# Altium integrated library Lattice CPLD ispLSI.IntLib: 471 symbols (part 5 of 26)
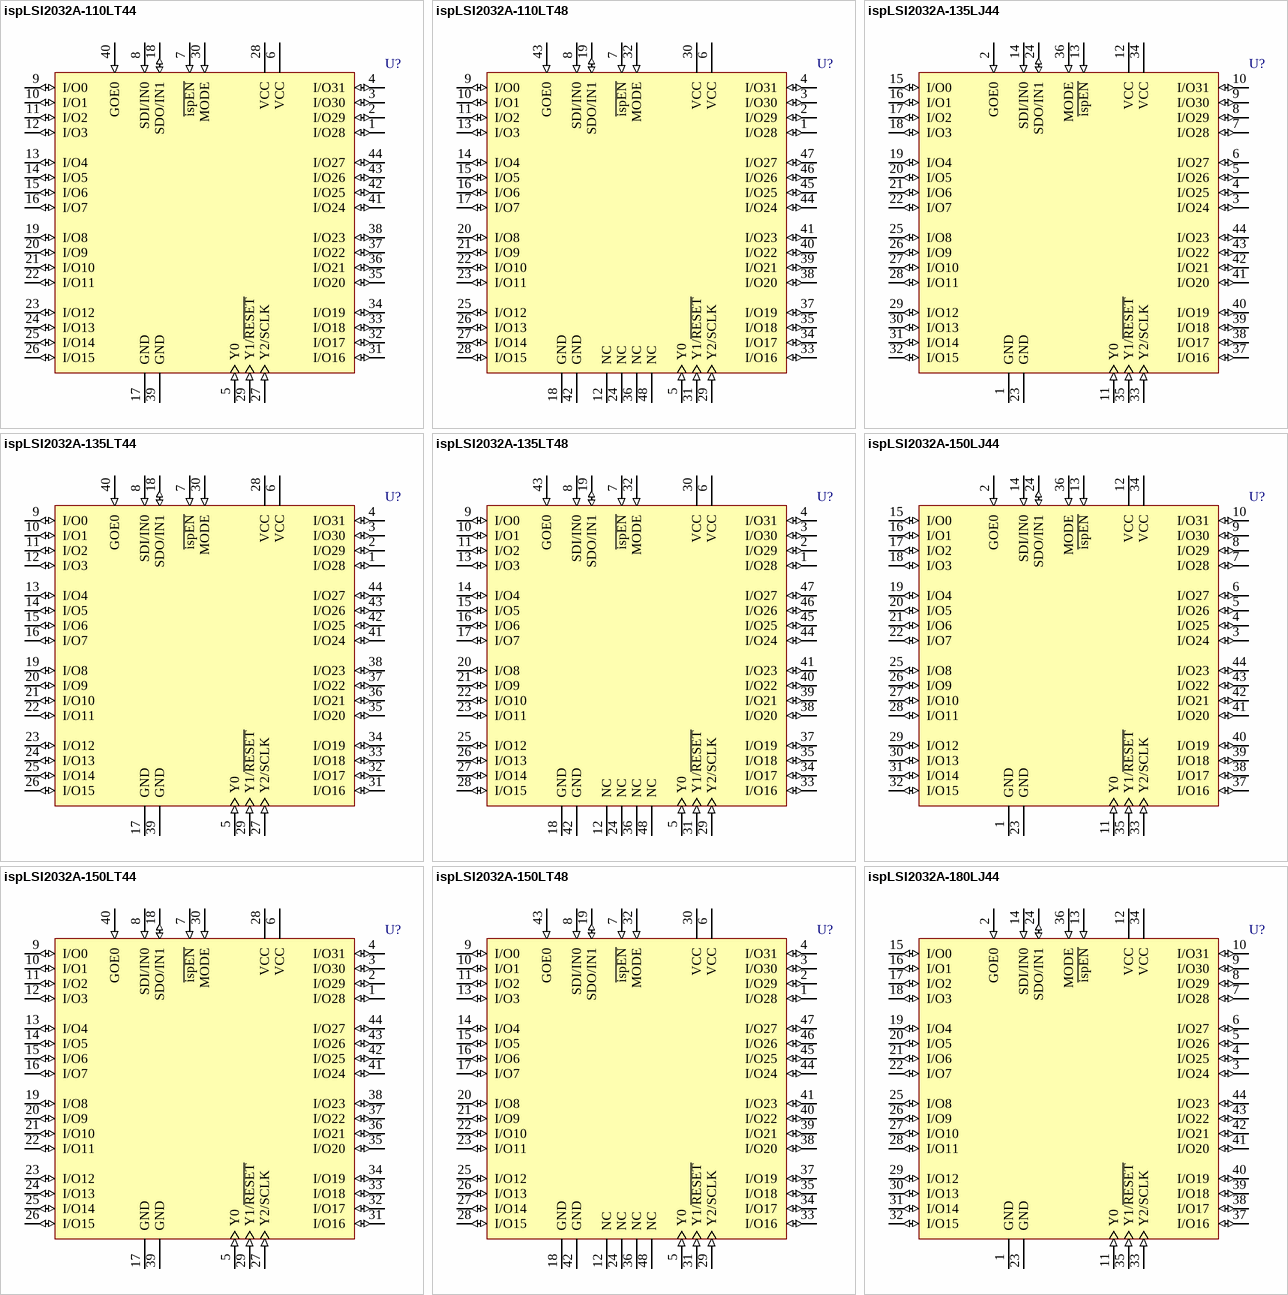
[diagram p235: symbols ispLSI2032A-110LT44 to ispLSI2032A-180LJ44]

## ispLSI2032A-150LT44
designator U?
In-System Programmable High-Density PLD; Note: Pins 8, 18 and 27 have dual function capability.
footprint TQFP44_N (Thin QFP, 44-Leads, Body 10x10mm, Pitch 0.8mm, IPC Medium Density)
footprint TQFP44_L (Thin QFP, 44-Leads, Body 10x10mm, Pitch 0.8mm, IPC High Density)
footprint TQFP44_M (Thin QFP, 44-Leads, Body 10x10mm, Pitch 0.8mm, IPC Low Density)
3D model 2032A-TQFP44 (44-Pin Thin Quad Flat Pack 0.8 mm Pitch)
pins: 1 I/O28 (io), 2 I/O29 (io), 3 I/O30 (io), 4 I/O31 (io), 5 Y0 (in), 6 VCC (power), 7 ~{ispEN} (in), 8 SDI/IN0 (in), 9 I/O0 (io), 10 I/O1 (io), 11 I/O2 (io), 12 I/O3 (io), 13 I/O4 (io), 14 I/O5 (io), 15 I/O6 (io), 16 I/O7 (io), 17 GND (power), 18 SDO/IN1 (io), 19 I/O8 (io), 20 I/O9 (io), 21 I/O10 (io), 22 I/O11 (io), 23 I/O12 (io), 24 I/O13 (io), 25 I/O14 (io), 26 I/O15 (io), 27 Y2/SCLK (in), 28 VCC (power), 29 Y1/~{RESET} (in), 30 MODE (in), 31 I/O16 (io), 32 I/O17 (io), 33 I/O18 (io), 34 I/O19 (io), 35 I/O20 (io), 36 I/O21 (io), 37 I/O22 (io), 38 I/O23 (io), 39 GND (power), 40 GOE0 (in), 41 I/O24 (io), 42 I/O25 (io), 43 I/O26 (io), 44 I/O27 (io)

## ispLSI2032A-150LT48
designator U?
In-System Programmable High-Density PLD; Note: Pins 8, 19 and 29 have dual function capability.
footprint TQFP48_N (Thin QFP, 48-Leads, Body 7x7mm, Pitch 0.5mm, IPC Medium Density)
footprint TQFP48_L (Thin QFP, 48-Leads, Body 7x7mm, Pitch 0.5mm, IPC High Density)
footprint TQFP48_M (Thin QFP, 48-Leads, Body 7x7mm, Pitch 0.5mm, IPC Low Density)
3D model 2032A-TQFP48 (48-Pin Thin Quad Flat Pack 0.5 mm Pitch)
pins: 1 I/O28 (io), 2 I/O29 (io), 3 I/O30 (io), 4 I/O31 (io), 5 Y0 (in), 6 VCC (power), 7 ~{ispEN} (in), 8 SDI/IN0 (in), 9 I/O0 (io), 10 I/O1 (io), 11 I/O2 (io), 12 NC, 13 I/O3 (io), 14 I/O4 (io), 15 I/O5 (io), 16 I/O6 (io), 17 I/O7 (io), 18 GND (power), 19 SDO/IN1 (io), 20 I/O8 (io), 21 I/O9 (io), 22 I/O10 (io), 23 I/O11 (io), 24 NC, 25 I/O12 (io), 26 I/O13 (io), 27 I/O14 (io), 28 I/O15 (io), 29 Y2/SCLK (in), 30 VCC (power), 31 Y1/~{RESET} (in), 32 MODE (in), 33 I/O16 (io), 34 I/O17 (io), 35 I/O18 (io), 36 NC, 37 I/O19 (io), 38 I/O20 (io), 39 I/O21 (io), 40 I/O22 (io), 41 I/O23 (io), 42 GND (power), 43 GOE0 (in), 44 I/O24 (io), 45 I/O25 (io), 46 I/O26 (io), 47 I/O27 (io), 48 NC

## ispLSI2032A-180LJ44
designator U?
In-System Programmable High-Density PLD; Note: Pins 14, 24 and 33 have dual function capability.
footprint PLCC44_N (Leaded Chip Carrier, 44-Leads, Body 16.6x16.6mm, Pitch 1.27mm, IPC Medium Density)
footprint PLCC44_L (Leaded Chip Carrier, 44-Leads, Body 16.6x16.6mm, Pitch 1.27mm, IPC High Density)
footprint PLCC44_M (Leaded Chip Carrier, 44-Leads, Body 16.6x16.6mm, Pitch 1.27mm, IPC Low Density)
3D model 2032A-PLCC44 (44-Pin Leaded Chip Carrier 1.27 mm Pitch)
pins: 1 GND (power), 2 GOE0 (in), 3 I/O24 (io), 4 I/O25 (io), 5 I/O26 (io), 6 I/O27 (io), 7 I/O28 (io), 8 I/O29 (io), 9 I/O30 (io), 10 I/O31 (io), 11 Y0 (in), 12 VCC (power), 13 ~{ispEN} (in), 14 SDI/IN0 (in), 15 I/O0 (io), 16 I/O1 (io), 17 I/O2 (io), 18 I/O3 (io), 19 I/O4 (io), 20 I/O5 (io), 21 I/O6 (io), 22 I/O7 (io), 23 GND (power), 24 SDO/IN1 (io), 25 I/O8 (io), 26 I/O9 (io), 27 I/O10 (io), 28 I/O11 (io), 29 I/O12 (io), 30 I/O13 (io), 31 I/O14 (io), 32 I/O15 (io), 33 Y2/SCLK (in), 34 VCC (power), 35 Y1/~{RESET} (in), 36 MODE (in), 37 I/O16 (io), 38 I/O17 (io), 39 I/O18 (io), 40 I/O19 (io), 41 I/O20 (io), 42 I/O21 (io), 43 I/O22 (io), 44 I/O23 (io)

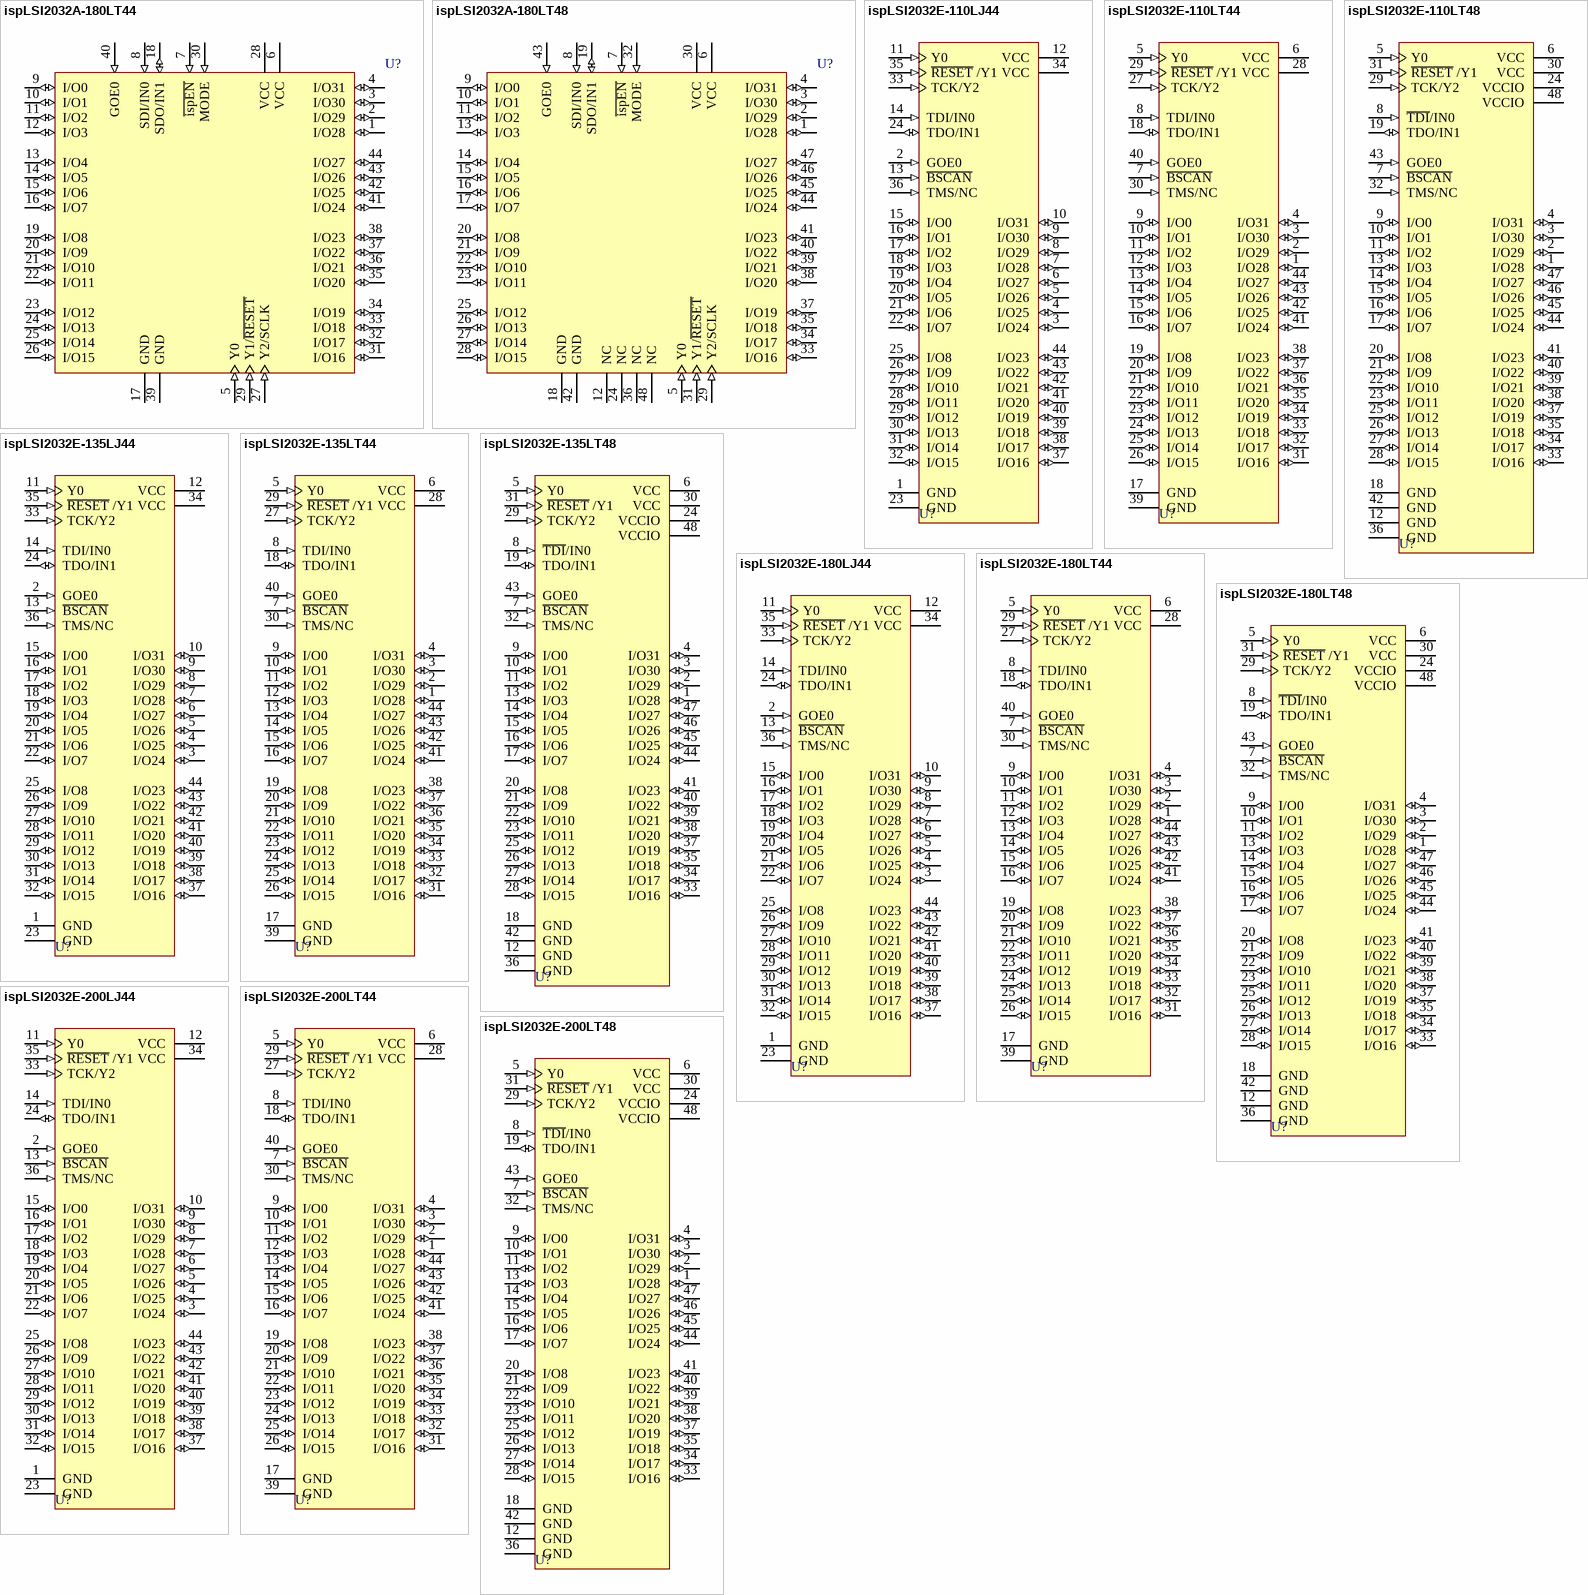
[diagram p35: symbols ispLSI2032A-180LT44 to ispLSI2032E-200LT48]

## ispLSI2032A-180LT44
designator U?
In-System Programmable High-Density PLD; Note: Pins 8, 18 and 27 have dual function capability.
footprint TQFP44_N (Thin QFP, 44-Leads, Body 10x10mm, Pitch 0.8mm, IPC Medium Density)
footprint TQFP44_L (Thin QFP, 44-Leads, Body 10x10mm, Pitch 0.8mm, IPC High Density)
footprint TQFP44_M (Thin QFP, 44-Leads, Body 10x10mm, Pitch 0.8mm, IPC Low Density)
3D model 2032A-TQFP44 (44-Pin Thin Quad Flat Pack 0.8 mm Pitch)
pins: 1 I/O28 (io), 2 I/O29 (io), 3 I/O30 (io), 4 I/O31 (io), 5 Y0 (in), 6 VCC (power), 7 ~{ispEN} (in), 8 SDI/IN0 (in), 9 I/O0 (io), 10 I/O1 (io), 11 I/O2 (io), 12 I/O3 (io), 13 I/O4 (io), 14 I/O5 (io), 15 I/O6 (io), 16 I/O7 (io), 17 GND (power), 18 SDO/IN1 (io), 19 I/O8 (io), 20 I/O9 (io), 21 I/O10 (io), 22 I/O11 (io), 23 I/O12 (io), 24 I/O13 (io), 25 I/O14 (io), 26 I/O15 (io), 27 Y2/SCLK (in), 28 VCC (power), 29 Y1/~{RESET} (in), 30 MODE (in), 31 I/O16 (io), 32 I/O17 (io), 33 I/O18 (io), 34 I/O19 (io), 35 I/O20 (io), 36 I/O21 (io), 37 I/O22 (io), 38 I/O23 (io), 39 GND (power), 40 GOE0 (in), 41 I/O24 (io), 42 I/O25 (io), 43 I/O26 (io), 44 I/O27 (io)

## ispLSI2032A-180LT48
designator U?
In-System Programmable High-Density PLD; Note: Pins 8, 19 and 29 have dual function capability.
footprint TQFP48_N (Thin QFP, 48-Leads, Body 7x7mm, Pitch 0.5mm, IPC Medium Density)
footprint TQFP48_L (Thin QFP, 48-Leads, Body 7x7mm, Pitch 0.5mm, IPC High Density)
footprint TQFP48_M (Thin QFP, 48-Leads, Body 7x7mm, Pitch 0.5mm, IPC Low Density)
3D model 2032A-TQFP48 (48-Pin Thin Quad Flat Pack 0.5 mm Pitch)
pins: 1 I/O28 (io), 2 I/O29 (io), 3 I/O30 (io), 4 I/O31 (io), 5 Y0 (in), 6 VCC (power), 7 ~{ispEN} (in), 8 SDI/IN0 (in), 9 I/O0 (io), 10 I/O1 (io), 11 I/O2 (io), 12 NC, 13 I/O3 (io), 14 I/O4 (io), 15 I/O5 (io), 16 I/O6 (io), 17 I/O7 (io), 18 GND (power), 19 SDO/IN1 (io), 20 I/O8 (io), 21 I/O9 (io), 22 I/O10 (io), 23 I/O11 (io), 24 NC, 25 I/O12 (io), 26 I/O13 (io), 27 I/O14 (io), 28 I/O15 (io), 29 Y2/SCLK (in), 30 VCC (power), 31 Y1/~{RESET} (in), 32 MODE (in), 33 I/O16 (io), 34 I/O17 (io), 35 I/O18 (io), 36 NC, 37 I/O19 (io), 38 I/O20 (io), 39 I/O21 (io), 40 I/O22 (io), 41 I/O23 (io), 42 GND (power), 43 GOE0 (in), 44 I/O24 (io), 45 I/O25 (io), 46 I/O26 (io), 47 I/O27 (io), 48 NC

## ispLSI2032E-110LJ44
designator U?
In-System Programmable SuperFAST High Density PLD
footprint PLCC44_N (Leaded Chip Carrier, 44-Leads, Body 16.6x16.6mm, Pitch 1.27mm, IPC Medium Density)
footprint PLCC44_L (Leaded Chip Carrier, 44-Leads, Body 16.6x16.6mm, Pitch 1.27mm, IPC High Density)
footprint PLCC44_M (Leaded Chip Carrier, 44-Leads, Body 16.6x16.6mm, Pitch 1.27mm, IPC Low Density)
3D model 2032E-PLCC44 (44-Pin Leaded Chip Carrier 1.27 mm Pitch)
pins: 1 GND (power), 2 GOE0 (in), 3 I/O24 (io), 4 I/O25 (io), 5 I/O26 (io), 6 I/O27 (io), 7 I/O28 (io), 8 I/O29 (io), 9 I/O30 (io), 10 I/O31 (io), 11 Y0 (in), 12 VCC (power), 13 ~{BSCAN} (in), 14 TDI/IN0 (in), 15 I/O0 (io), 16 I/O1 (io), 17 I/O2 (io), 18 I/O3 (io), 19 I/O4 (io), 20 I/O5 (io), 21 I/O6 (io), 22 I/O7 (io), 23 GND (power), 24 TDO/IN1 (io), 25 I/O8 (io), 26 I/O9 (io), 27 I/O10 (io), 28 I/O11 (io), 29 I/O12 (io), 30 I/O13 (io), 31 I/O14 (io), 32 I/O15 (io), 33 TCK/Y2 (in), 34 VCC (power), 35 ~{RESET} /Y1 (in), 36 TMS/NC (in), 37 I/O16 (io), 38 I/O17 (io), 39 I/O18 (io), 40 I/O19 (io), 41 I/O20 (io), 42 I/O21 (io), 43 I/O22 (io), 44 I/O23 (io)

## ispLSI2032E-110LT44
designator U?
In-System Programmable SuperFAST High Density PLD
footprint TQFP44_N (Thin QFP, 44-Leads, Body 10x10mm, Pitch 0.8mm, IPC Medium Density)
footprint TQFP44_L (Thin QFP, 44-Leads, Body 10x10mm, Pitch 0.8mm, IPC High Density)
footprint TQFP44_M (Thin QFP, 44-Leads, Body 10x10mm, Pitch 0.8mm, IPC Low Density)
3D model 2032E-TQFP44 (44-Pin Thin Quad Flat Pack 0.8 mm Pitch)
pins: 1 I/O28 (io), 2 I/O29 (io), 3 I/O30 (io), 4 I/O31 (io), 5 Y0 (in), 6 VCC (power), 7 ~{BSCAN} (in), 8 TDI/IN0 (in), 9 I/O0 (io), 10 I/O1 (io), 11 I/O2 (io), 12 I/O3 (io), 13 I/O4 (io), 14 I/O5 (io), 15 I/O6 (io), 16 I/O7 (io), 17 GND (power), 18 TDO/IN1 (io), 19 I/O8 (io), 20 I/O9 (io), 21 I/O10 (io), 22 I/O11 (io), 23 I/O12 (io), 24 I/O13 (io), 25 I/O14 (io), 26 I/O15 (io), 27 TCK/Y2 (in), 28 VCC (power), 29 ~{RESET} /Y1 (in), 30 TMS/NC (in), 31 I/O16 (io), 32 I/O17 (io), 33 I/O18 (io), 34 I/O19 (io), 35 I/O20 (io), 36 I/O21 (io), 37 I/O22 (io), 38 I/O23 (io), 39 GND (power), 40 GOE0 (in), 41 I/O24 (io), 42 I/O25 (io), 43 I/O26 (io), 44 I/O27 (io)

## ispLSI2032E-110LT48
designator U?
In-System Programmable SuperFAST High Density PLD
footprint TQFP48_N (Thin QFP, 48-Leads, Body 7x7mm, Pitch 0.5mm, IPC Medium Density)
footprint TQFP48_L (Thin QFP, 48-Leads, Body 7x7mm, Pitch 0.5mm, IPC High Density)
footprint TQFP48_M (Thin QFP, 48-Leads, Body 7x7mm, Pitch 0.5mm, IPC Low Density)
3D model 2032E-TQFP48 (48-Pin Thin Quad Flat Pack 0.5 mm Pitch)
pins: 1 I/O28 (io), 2 I/O29 (io), 3 I/O30 (io), 4 I/O31 (io), 5 Y0 (in), 6 VCC (power), 7 ~{BSCAN} (in), 8 ~{TDI}/IN0 (in), 9 I/O0 (io), 10 I/O1 (io), 11 I/O2 (io), 12 GND (power), 13 I/O3 (io), 14 I/O4 (io), 15 I/O5 (io), 16 I/O6 (io), 17 I/O7 (io), 18 GND (power), 19 TDO/IN1 (io), 20 I/O8 (io), 21 I/O9 (io), 22 I/O10 (io), 23 I/O11 (io), 24 VCCIO (power), 25 I/O12 (io), 26 I/O13 (io), 27 I/O14 (io), 28 I/O15 (io), 29 TCK/Y2 (in), 30 VCC (power), 31 ~{RESET} /Y1 (in), 32 TMS/NC (in), 33 I/O16 (io), 34 I/O17 (io), 35 I/O18 (io), 36 GND (power), 37 I/O19 (io), 38 I/O20 (io), 39 I/O21 (io), 40 I/O22 (io), 41 I/O23 (io), 42 GND (power), 43 GOE0 (in), 44 I/O24 (io), 45 I/O25 (io), 46 I/O26 (io), 47 I/O27 (io), 48 VCCIO (power)

## ispLSI2032E-135LJ44
designator U?
In-System Programmable SuperFAST High Density PLD
footprint PLCC44_N (Leaded Chip Carrier, 44-Leads, Body 16.6x16.6mm, Pitch 1.27mm, IPC Medium Density)
footprint PLCC44_L (Leaded Chip Carrier, 44-Leads, Body 16.6x16.6mm, Pitch 1.27mm, IPC High Density)
footprint PLCC44_M (Leaded Chip Carrier, 44-Leads, Body 16.6x16.6mm, Pitch 1.27mm, IPC Low Density)
3D model 2032E-PLCC44 (44-Pin Leaded Chip Carrier 1.27 mm Pitch)
pins: 1 GND (power), 2 GOE0 (in), 3 I/O24 (io), 4 I/O25 (io), 5 I/O26 (io), 6 I/O27 (io), 7 I/O28 (io), 8 I/O29 (io), 9 I/O30 (io), 10 I/O31 (io), 11 Y0 (in), 12 VCC (power), 13 ~{BSCAN} (in), 14 TDI/IN0 (in), 15 I/O0 (io), 16 I/O1 (io), 17 I/O2 (io), 18 I/O3 (io), 19 I/O4 (io), 20 I/O5 (io), 21 I/O6 (io), 22 I/O7 (io), 23 GND (power), 24 TDO/IN1 (io), 25 I/O8 (io), 26 I/O9 (io), 27 I/O10 (io), 28 I/O11 (io), 29 I/O12 (io), 30 I/O13 (io), 31 I/O14 (io), 32 I/O15 (io), 33 TCK/Y2 (in), 34 VCC (power), 35 ~{RESET} /Y1 (in), 36 TMS/NC (in), 37 I/O16 (io), 38 I/O17 (io), 39 I/O18 (io), 40 I/O19 (io), 41 I/O20 (io), 42 I/O21 (io), 43 I/O22 (io), 44 I/O23 (io)

## ispLSI2032E-135LT44
designator U?
In-System Programmable SuperFAST High Density PLD
footprint TQFP44_N (Thin QFP, 44-Leads, Body 10x10mm, Pitch 0.8mm, IPC Medium Density)
footprint TQFP44_L (Thin QFP, 44-Leads, Body 10x10mm, Pitch 0.8mm, IPC High Density)
footprint TQFP44_M (Thin QFP, 44-Leads, Body 10x10mm, Pitch 0.8mm, IPC Low Density)
3D model 2032E-TQFP44 (44-Pin Thin Quad Flat Pack 0.8 mm Pitch)
pins: 1 I/O28 (io), 2 I/O29 (io), 3 I/O30 (io), 4 I/O31 (io), 5 Y0 (in), 6 VCC (power), 7 ~{BSCAN} (in), 8 TDI/IN0 (in), 9 I/O0 (io), 10 I/O1 (io), 11 I/O2 (io), 12 I/O3 (io), 13 I/O4 (io), 14 I/O5 (io), 15 I/O6 (io), 16 I/O7 (io), 17 GND (power), 18 TDO/IN1 (io), 19 I/O8 (io), 20 I/O9 (io), 21 I/O10 (io), 22 I/O11 (io), 23 I/O12 (io), 24 I/O13 (io), 25 I/O14 (io), 26 I/O15 (io), 27 TCK/Y2 (in), 28 VCC (power), 29 ~{RESET} /Y1 (in), 30 TMS/NC (in), 31 I/O16 (io), 32 I/O17 (io), 33 I/O18 (io), 34 I/O19 (io), 35 I/O20 (io), 36 I/O21 (io), 37 I/O22 (io), 38 I/O23 (io), 39 GND (power), 40 GOE0 (in), 41 I/O24 (io), 42 I/O25 (io), 43 I/O26 (io), 44 I/O27 (io)

## ispLSI2032E-135LT48
designator U?
In-System Programmable SuperFAST High Density PLD
footprint TQFP48_N (Thin QFP, 48-Leads, Body 7x7mm, Pitch 0.5mm, IPC Medium Density)
footprint TQFP48_L (Thin QFP, 48-Leads, Body 7x7mm, Pitch 0.5mm, IPC High Density)
footprint TQFP48_M (Thin QFP, 48-Leads, Body 7x7mm, Pitch 0.5mm, IPC Low Density)
3D model 2032E-TQFP48 (48-Pin Thin Quad Flat Pack 0.5 mm Pitch)
pins: 1 I/O28 (io), 2 I/O29 (io), 3 I/O30 (io), 4 I/O31 (io), 5 Y0 (in), 6 VCC (power), 7 ~{BSCAN} (in), 8 ~{TDI}/IN0 (in), 9 I/O0 (io), 10 I/O1 (io), 11 I/O2 (io), 12 GND (power), 13 I/O3 (io), 14 I/O4 (io), 15 I/O5 (io), 16 I/O6 (io), 17 I/O7 (io), 18 GND (power), 19 TDO/IN1 (io), 20 I/O8 (io), 21 I/O9 (io), 22 I/O10 (io), 23 I/O11 (io), 24 VCCIO (power), 25 I/O12 (io), 26 I/O13 (io), 27 I/O14 (io), 28 I/O15 (io), 29 TCK/Y2 (in), 30 VCC (power), 31 ~{RESET} /Y1 (in), 32 TMS/NC (in), 33 I/O16 (io), 34 I/O17 (io), 35 I/O18 (io), 36 GND (power), 37 I/O19 (io), 38 I/O20 (io), 39 I/O21 (io), 40 I/O22 (io), 41 I/O23 (io), 42 GND (power), 43 GOE0 (in), 44 I/O24 (io), 45 I/O25 (io), 46 I/O26 (io), 47 I/O27 (io), 48 VCCIO (power)

## ispLSI2032E-180LJ44
designator U?
In-System Programmable SuperFAST High Density PLD
footprint PLCC44_N (Leaded Chip Carrier, 44-Leads, Body 16.6x16.6mm, Pitch 1.27mm, IPC Medium Density)
footprint PLCC44_L (Leaded Chip Carrier, 44-Leads, Body 16.6x16.6mm, Pitch 1.27mm, IPC High Density)
footprint PLCC44_M (Leaded Chip Carrier, 44-Leads, Body 16.6x16.6mm, Pitch 1.27mm, IPC Low Density)
3D model 2032E-PLCC44 (44-Pin Leaded Chip Carrier 1.27 mm Pitch)
pins: 1 GND (power), 2 GOE0 (in), 3 I/O24 (io), 4 I/O25 (io), 5 I/O26 (io), 6 I/O27 (io), 7 I/O28 (io), 8 I/O29 (io), 9 I/O30 (io), 10 I/O31 (io), 11 Y0 (in), 12 VCC (power), 13 ~{BSCAN} (in), 14 TDI/IN0 (in), 15 I/O0 (io), 16 I/O1 (io), 17 I/O2 (io), 18 I/O3 (io), 19 I/O4 (io), 20 I/O5 (io), 21 I/O6 (io), 22 I/O7 (io), 23 GND (power), 24 TDO/IN1 (io), 25 I/O8 (io), 26 I/O9 (io), 27 I/O10 (io), 28 I/O11 (io), 29 I/O12 (io), 30 I/O13 (io), 31 I/O14 (io), 32 I/O15 (io), 33 TCK/Y2 (in), 34 VCC (power), 35 ~{RESET} /Y1 (in), 36 TMS/NC (in), 37 I/O16 (io), 38 I/O17 (io), 39 I/O18 (io), 40 I/O19 (io), 41 I/O20 (io), 42 I/O21 (io), 43 I/O22 (io), 44 I/O23 (io)

## ispLSI2032E-180LT44
designator U?
In-System Programmable SuperFAST High Density PLD
footprint TQFP44_N (Thin QFP, 44-Leads, Body 10x10mm, Pitch 0.8mm, IPC Medium Density)
footprint TQFP44_L (Thin QFP, 44-Leads, Body 10x10mm, Pitch 0.8mm, IPC High Density)
footprint TQFP44_M (Thin QFP, 44-Leads, Body 10x10mm, Pitch 0.8mm, IPC Low Density)
3D model 2032E-TQFP44 (44-Pin Thin Quad Flat Pack 0.8 mm Pitch)
pins: 1 I/O28 (io), 2 I/O29 (io), 3 I/O30 (io), 4 I/O31 (io), 5 Y0 (in), 6 VCC (power), 7 ~{BSCAN} (in), 8 TDI/IN0 (in), 9 I/O0 (io), 10 I/O1 (io), 11 I/O2 (io), 12 I/O3 (io), 13 I/O4 (io), 14 I/O5 (io), 15 I/O6 (io), 16 I/O7 (io), 17 GND (power), 18 TDO/IN1 (io), 19 I/O8 (io), 20 I/O9 (io), 21 I/O10 (io), 22 I/O11 (io), 23 I/O12 (io), 24 I/O13 (io), 25 I/O14 (io), 26 I/O15 (io), 27 TCK/Y2 (in), 28 VCC (power), 29 ~{RESET} /Y1 (in), 30 TMS/NC (in), 31 I/O16 (io), 32 I/O17 (io), 33 I/O18 (io), 34 I/O19 (io), 35 I/O20 (io), 36 I/O21 (io), 37 I/O22 (io), 38 I/O23 (io), 39 GND (power), 40 GOE0 (in), 41 I/O24 (io), 42 I/O25 (io), 43 I/O26 (io), 44 I/O27 (io)

## ispLSI2032E-180LT48
designator U?
In-System Programmable SuperFAST High Density PLD
footprint TQFP48_N (Thin QFP, 48-Leads, Body 7x7mm, Pitch 0.5mm, IPC Medium Density)
footprint TQFP48_L (Thin QFP, 48-Leads, Body 7x7mm, Pitch 0.5mm, IPC High Density)
footprint TQFP48_M (Thin QFP, 48-Leads, Body 7x7mm, Pitch 0.5mm, IPC Low Density)
3D model 2032E-TQFP48 (48-Pin Thin Quad Flat Pack 0.5 mm Pitch)
pins: 1 I/O28 (io), 2 I/O29 (io), 3 I/O30 (io), 4 I/O31 (io), 5 Y0 (in), 6 VCC (power), 7 ~{BSCAN} (in), 8 ~{TDI}/IN0 (in), 9 I/O0 (io), 10 I/O1 (io), 11 I/O2 (io), 12 GND (power), 13 I/O3 (io), 14 I/O4 (io), 15 I/O5 (io), 16 I/O6 (io), 17 I/O7 (io), 18 GND (power), 19 TDO/IN1 (io), 20 I/O8 (io), 21 I/O9 (io), 22 I/O10 (io), 23 I/O11 (io), 24 VCCIO (power), 25 I/O12 (io), 26 I/O13 (io), 27 I/O14 (io), 28 I/O15 (io), 29 TCK/Y2 (in), 30 VCC (power), 31 ~{RESET} /Y1 (in), 32 TMS/NC (in), 33 I/O16 (io), 34 I/O17 (io), 35 I/O18 (io), 36 GND (power), 37 I/O19 (io), 38 I/O20 (io), 39 I/O21 (io), 40 I/O22 (io), 41 I/O23 (io), 42 GND (power), 43 GOE0 (in), 44 I/O24 (io), 45 I/O25 (io), 46 I/O26 (io), 47 I/O27 (io), 48 VCCIO (power)

## ispLSI2032E-200LJ44
designator U?
In-System Programmable SuperFAST High Density PLD
footprint PLCC44_N (Leaded Chip Carrier, 44-Leads, Body 16.6x16.6mm, Pitch 1.27mm, IPC Medium Density)
footprint PLCC44_L (Leaded Chip Carrier, 44-Leads, Body 16.6x16.6mm, Pitch 1.27mm, IPC High Density)
footprint PLCC44_M (Leaded Chip Carrier, 44-Leads, Body 16.6x16.6mm, Pitch 1.27mm, IPC Low Density)
3D model 2032E-PLCC44 (44-Pin Leaded Chip Carrier 1.27 mm Pitch)
pins: 1 GND (power), 2 GOE0 (in), 3 I/O24 (io), 4 I/O25 (io), 5 I/O26 (io), 6 I/O27 (io), 7 I/O28 (io), 8 I/O29 (io), 9 I/O30 (io), 10 I/O31 (io), 11 Y0 (in), 12 VCC (power), 13 ~{BSCAN} (in), 14 TDI/IN0 (in), 15 I/O0 (io), 16 I/O1 (io), 17 I/O2 (io), 18 I/O3 (io), 19 I/O4 (io), 20 I/O5 (io), 21 I/O6 (io), 22 I/O7 (io), 23 GND (power), 24 TDO/IN1 (io), 25 I/O8 (io), 26 I/O9 (io), 27 I/O10 (io), 28 I/O11 (io), 29 I/O12 (io), 30 I/O13 (io), 31 I/O14 (io), 32 I/O15 (io), 33 TCK/Y2 (in), 34 VCC (power), 35 ~{RESET} /Y1 (in), 36 TMS/NC (in), 37 I/O16 (io), 38 I/O17 (io), 39 I/O18 (io), 40 I/O19 (io), 41 I/O20 (io), 42 I/O21 (io), 43 I/O22 (io), 44 I/O23 (io)

## ispLSI2032E-200LT44
designator U?
In-System Programmable SuperFAST High Density PLD
footprint TQFP44_N (Thin QFP, 44-Leads, Body 10x10mm, Pitch 0.8mm, IPC Medium Density)
footprint TQFP44_L (Thin QFP, 44-Leads, Body 10x10mm, Pitch 0.8mm, IPC High Density)
footprint TQFP44_M (Thin QFP, 44-Leads, Body 10x10mm, Pitch 0.8mm, IPC Low Density)
3D model 2032E-TQFP44 (44-Pin Thin Quad Flat Pack 0.8 mm Pitch)
pins: 1 I/O28 (io), 2 I/O29 (io), 3 I/O30 (io), 4 I/O31 (io), 5 Y0 (in), 6 VCC (power), 7 ~{BSCAN} (in), 8 TDI/IN0 (in), 9 I/O0 (io), 10 I/O1 (io), 11 I/O2 (io), 12 I/O3 (io), 13 I/O4 (io), 14 I/O5 (io), 15 I/O6 (io), 16 I/O7 (io), 17 GND (power), 18 TDO/IN1 (io), 19 I/O8 (io), 20 I/O9 (io), 21 I/O10 (io), 22 I/O11 (io), 23 I/O12 (io), 24 I/O13 (io), 25 I/O14 (io), 26 I/O15 (io), 27 TCK/Y2 (in), 28 VCC (power), 29 ~{RESET} /Y1 (in), 30 TMS/NC (in), 31 I/O16 (io), 32 I/O17 (io), 33 I/O18 (io), 34 I/O19 (io), 35 I/O20 (io), 36 I/O21 (io), 37 I/O22 (io), 38 I/O23 (io), 39 GND (power), 40 GOE0 (in), 41 I/O24 (io), 42 I/O25 (io), 43 I/O26 (io), 44 I/O27 (io)

## ispLSI2032E-200LT48
designator U?
In-System Programmable SuperFAST High Density PLD
footprint TQFP48_N (Thin QFP, 48-Leads, Body 7x7mm, Pitch 0.5mm, IPC Medium Density)
footprint TQFP48_L (Thin QFP, 48-Leads, Body 7x7mm, Pitch 0.5mm, IPC High Density)
footprint TQFP48_M (Thin QFP, 48-Leads, Body 7x7mm, Pitch 0.5mm, IPC Low Density)
3D model 2032E-TQFP48 (48-Pin Thin Quad Flat Pack 0.5 mm Pitch)
pins: 1 I/O28 (io), 2 I/O29 (io), 3 I/O30 (io), 4 I/O31 (io), 5 Y0 (in), 6 VCC (power), 7 ~{BSCAN} (in), 8 ~{TDI}/IN0 (in), 9 I/O0 (io), 10 I/O1 (io), 11 I/O2 (io), 12 GND (power), 13 I/O3 (io), 14 I/O4 (io), 15 I/O5 (io), 16 I/O6 (io), 17 I/O7 (io), 18 GND (power), 19 TDO/IN1 (io), 20 I/O8 (io), 21 I/O9 (io), 22 I/O10 (io), 23 I/O11 (io), 24 VCCIO (power), 25 I/O12 (io), 26 I/O13 (io), 27 I/O14 (io), 28 I/O15 (io), 29 TCK/Y2 (in), 30 VCC (power), 31 ~{RESET} /Y1 (in), 32 TMS/NC (in), 33 I/O16 (io), 34 I/O17 (io), 35 I/O18 (io), 36 GND (power), 37 I/O19 (io), 38 I/O20 (io), 39 I/O21 (io), 40 I/O22 (io), 41 I/O23 (io), 42 GND (power), 43 GOE0 (in), 44 I/O24 (io), 45 I/O25 (io), 46 I/O26 (io), 47 I/O27 (io), 48 VCCIO (power)

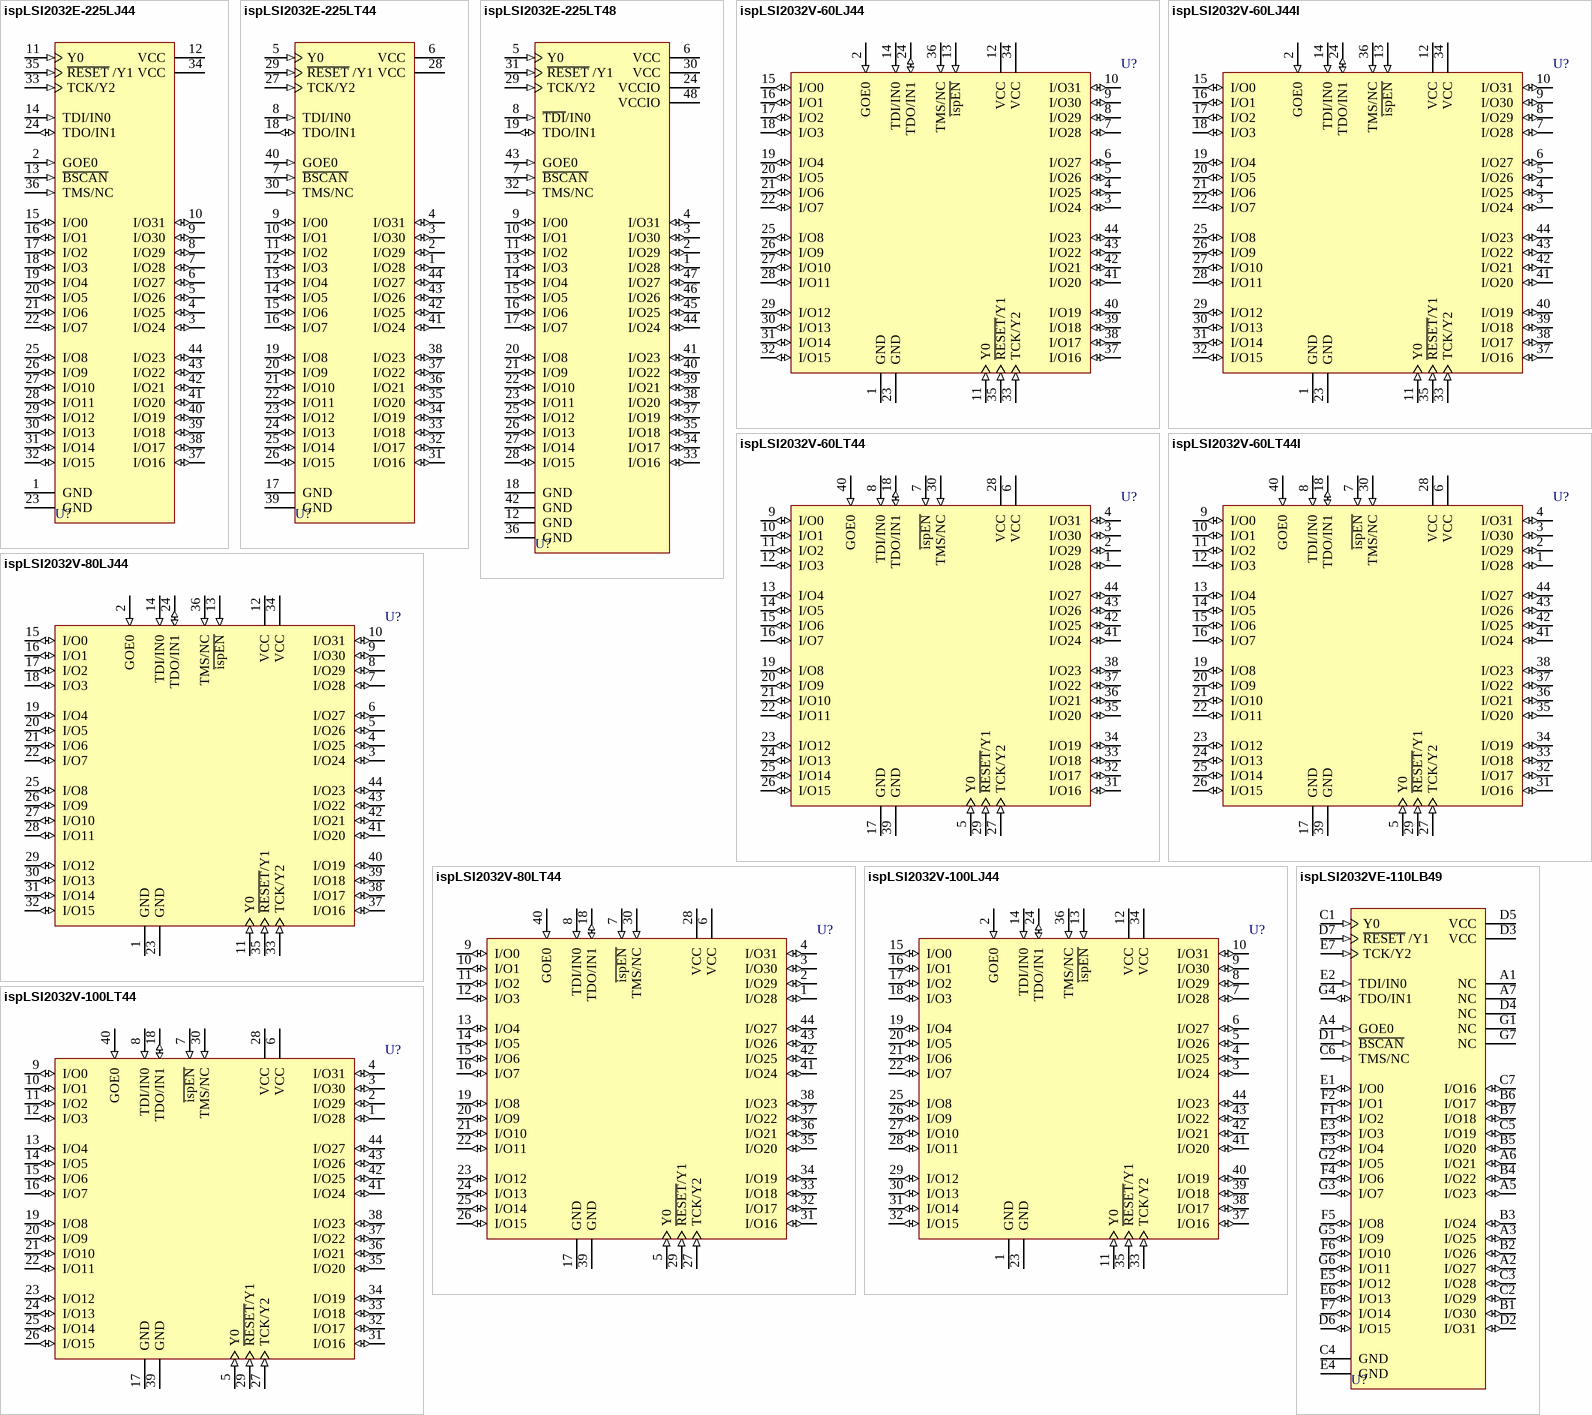
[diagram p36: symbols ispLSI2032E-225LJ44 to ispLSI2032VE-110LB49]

## ispLSI2032E-225LJ44
designator U?
In-System Programmable SuperFAST High Density PLD
footprint PLCC44_N (Leaded Chip Carrier, 44-Leads, Body 16.6x16.6mm, Pitch 1.27mm, IPC Medium Density)
footprint PLCC44_L (Leaded Chip Carrier, 44-Leads, Body 16.6x16.6mm, Pitch 1.27mm, IPC High Density)
footprint PLCC44_M (Leaded Chip Carrier, 44-Leads, Body 16.6x16.6mm, Pitch 1.27mm, IPC Low Density)
3D model 2032E-PLCC44 (44-Pin Leaded Chip Carrier 1.27 mm Pitch)
pins: 1 GND (power), 2 GOE0 (in), 3 I/O24 (io), 4 I/O25 (io), 5 I/O26 (io), 6 I/O27 (io), 7 I/O28 (io), 8 I/O29 (io), 9 I/O30 (io), 10 I/O31 (io), 11 Y0 (in), 12 VCC (power), 13 ~{BSCAN} (in), 14 TDI/IN0 (in), 15 I/O0 (io), 16 I/O1 (io), 17 I/O2 (io), 18 I/O3 (io), 19 I/O4 (io), 20 I/O5 (io), 21 I/O6 (io), 22 I/O7 (io), 23 GND (power), 24 TDO/IN1 (io), 25 I/O8 (io), 26 I/O9 (io), 27 I/O10 (io), 28 I/O11 (io), 29 I/O12 (io), 30 I/O13 (io), 31 I/O14 (io), 32 I/O15 (io), 33 TCK/Y2 (in), 34 VCC (power), 35 ~{RESET} /Y1 (in), 36 TMS/NC (in), 37 I/O16 (io), 38 I/O17 (io), 39 I/O18 (io), 40 I/O19 (io), 41 I/O20 (io), 42 I/O21 (io), 43 I/O22 (io), 44 I/O23 (io)

## ispLSI2032E-225LT44
designator U?
In-System Programmable SuperFAST High Density PLD
footprint TQFP44_N (Thin QFP, 44-Leads, Body 10x10mm, Pitch 0.8mm, IPC Medium Density)
footprint TQFP44_L (Thin QFP, 44-Leads, Body 10x10mm, Pitch 0.8mm, IPC High Density)
footprint TQFP44_M (Thin QFP, 44-Leads, Body 10x10mm, Pitch 0.8mm, IPC Low Density)
3D model 2032E-TQFP44 (44-Pin Thin Quad Flat Pack 0.8 mm Pitch)
pins: 1 I/O28 (io), 2 I/O29 (io), 3 I/O30 (io), 4 I/O31 (io), 5 Y0 (in), 6 VCC (power), 7 ~{BSCAN} (in), 8 TDI/IN0 (in), 9 I/O0 (io), 10 I/O1 (io), 11 I/O2 (io), 12 I/O3 (io), 13 I/O4 (io), 14 I/O5 (io), 15 I/O6 (io), 16 I/O7 (io), 17 GND (power), 18 TDO/IN1 (io), 19 I/O8 (io), 20 I/O9 (io), 21 I/O10 (io), 22 I/O11 (io), 23 I/O12 (io), 24 I/O13 (io), 25 I/O14 (io), 26 I/O15 (io), 27 TCK/Y2 (in), 28 VCC (power), 29 ~{RESET} /Y1 (in), 30 TMS/NC (in), 31 I/O16 (io), 32 I/O17 (io), 33 I/O18 (io), 34 I/O19 (io), 35 I/O20 (io), 36 I/O21 (io), 37 I/O22 (io), 38 I/O23 (io), 39 GND (power), 40 GOE0 (in), 41 I/O24 (io), 42 I/O25 (io), 43 I/O26 (io), 44 I/O27 (io)

## ispLSI2032E-225LT48
designator U?
In-System Programmable SuperFAST High Density PLD
footprint TQFP48_N (Thin QFP, 48-Leads, Body 7x7mm, Pitch 0.5mm, IPC Medium Density)
footprint TQFP48_L (Thin QFP, 48-Leads, Body 7x7mm, Pitch 0.5mm, IPC High Density)
footprint TQFP48_M (Thin QFP, 48-Leads, Body 7x7mm, Pitch 0.5mm, IPC Low Density)
3D model 2032E-TQFP48 (48-Pin Thin Quad Flat Pack 0.5 mm Pitch)
pins: 1 I/O28 (io), 2 I/O29 (io), 3 I/O30 (io), 4 I/O31 (io), 5 Y0 (in), 6 VCC (power), 7 ~{BSCAN} (in), 8 ~{TDI}/IN0 (in), 9 I/O0 (io), 10 I/O1 (io), 11 I/O2 (io), 12 GND (power), 13 I/O3 (io), 14 I/O4 (io), 15 I/O5 (io), 16 I/O6 (io), 17 I/O7 (io), 18 GND (power), 19 TDO/IN1 (io), 20 I/O8 (io), 21 I/O9 (io), 22 I/O10 (io), 23 I/O11 (io), 24 VCCIO (power), 25 I/O12 (io), 26 I/O13 (io), 27 I/O14 (io), 28 I/O15 (io), 29 TCK/Y2 (in), 30 VCC (power), 31 ~{RESET} /Y1 (in), 32 TMS/NC (in), 33 I/O16 (io), 34 I/O17 (io), 35 I/O18 (io), 36 GND (power), 37 I/O19 (io), 38 I/O20 (io), 39 I/O21 (io), 40 I/O22 (io), 41 I/O23 (io), 42 GND (power), 43 GOE0 (in), 44 I/O24 (io), 45 I/O25 (io), 46 I/O26 (io), 47 I/O27 (io), 48 VCCIO (power)

## ispLSI2032V-60LJ44
designator U?
3.3V High-Density Programmable Logic
footprint PLCC44_N (Leaded Chip Carrier, 44-Leads, Body 16.6x16.6mm, Pitch 1.27mm, IPC Medium Density)
footprint PLCC44_L (Leaded Chip Carrier, 44-Leads, Body 16.6x16.6mm, Pitch 1.27mm, IPC High Density)
footprint PLCC44_M (Leaded Chip Carrier, 44-Leads, Body 16.6x16.6mm, Pitch 1.27mm, IPC Low Density)
3D model 2032V-PLCC44 (44-Pin Leaded Chip Carrier 1.27 mm Pitch)
pins: 1 GND (power), 2 GOE0 (in), 3 I/O24 (io), 4 I/O25 (io), 5 I/O26 (io), 6 I/O27 (io), 7 I/O28 (io), 8 I/O29 (io), 9 I/O30 (io), 10 I/O31 (io), 11 Y0 (in), 12 VCC (power), 13 ~{ispEN} (in), 14 TDI/IN0 (in), 15 I/O0 (io), 16 I/O1 (io), 17 I/O2 (io), 18 I/O3 (io), 19 I/O4 (io), 20 I/O5 (io), 21 I/O6 (io), 22 I/O7 (io), 23 GND (power), 24 TDO/IN1 (io), 25 I/O8 (io), 26 I/O9 (io), 27 I/O10 (io), 28 I/O11 (io), 29 I/O12 (io), 30 I/O13 (io), 31 I/O14 (io), 32 I/O15 (io), 33 TCK/Y2 (in), 34 VCC (power), 35 ~{RESET}/Y1 (in), 36 TMS/NC (in), 37 I/O16 (io), 38 I/O17 (io), 39 I/O18 (io), 40 I/O19 (io), 41 I/O20 (io), 42 I/O21 (io), 43 I/O22 (io), 44 I/O23 (io)

## ispLSI2032V-60LJ44I
designator U?
3.3V High-Density Programmable Logic
footprint PLCC44_N (Leaded Chip Carrier, 44-Leads, Body 16.6x16.6mm, Pitch 1.27mm, IPC Medium Density)
footprint PLCC44_L (Leaded Chip Carrier, 44-Leads, Body 16.6x16.6mm, Pitch 1.27mm, IPC High Density)
footprint PLCC44_M (Leaded Chip Carrier, 44-Leads, Body 16.6x16.6mm, Pitch 1.27mm, IPC Low Density)
3D model 2032V-PLCC44 (44-Pin Leaded Chip Carrier 1.27 mm Pitch)
pins: 1 GND (power), 2 GOE0 (in), 3 I/O24 (io), 4 I/O25 (io), 5 I/O26 (io), 6 I/O27 (io), 7 I/O28 (io), 8 I/O29 (io), 9 I/O30 (io), 10 I/O31 (io), 11 Y0 (in), 12 VCC (power), 13 ~{ispEN} (in), 14 TDI/IN0 (in), 15 I/O0 (io), 16 I/O1 (io), 17 I/O2 (io), 18 I/O3 (io), 19 I/O4 (io), 20 I/O5 (io), 21 I/O6 (io), 22 I/O7 (io), 23 GND (power), 24 TDO/IN1 (io), 25 I/O8 (io), 26 I/O9 (io), 27 I/O10 (io), 28 I/O11 (io), 29 I/O12 (io), 30 I/O13 (io), 31 I/O14 (io), 32 I/O15 (io), 33 TCK/Y2 (in), 34 VCC (power), 35 ~{RESET}/Y1 (in), 36 TMS/NC (in), 37 I/O16 (io), 38 I/O17 (io), 39 I/O18 (io), 40 I/O19 (io), 41 I/O20 (io), 42 I/O21 (io), 43 I/O22 (io), 44 I/O23 (io)

## ispLSI2032V-60LT44
designator U?
3.3V High-Density Programmable Logic
footprint TQFP44_N (Thin QFP, 44-Leads, Body 10x10mm, Pitch 0.8mm, IPC Medium Density)
footprint TQFP44_L (Thin QFP, 44-Leads, Body 10x10mm, Pitch 0.8mm, IPC High Density)
footprint TQFP44_M (Thin QFP, 44-Leads, Body 10x10mm, Pitch 0.8mm, IPC Low Density)
3D model 2032V-TQFP44 (44-Pin Thin Quad Flat Pack 0.8 mm Pitch)
pins: 1 I/O28 (io), 2 I/O29 (io), 3 I/O30 (io), 4 I/O31 (io), 5 Y0 (in), 6 VCC (power), 7 ~{ispEN} (in), 8 TDI/IN0 (in), 9 I/O0 (io), 10 I/O1 (io), 11 I/O2 (io), 12 I/O3 (io), 13 I/O4 (io), 14 I/O5 (io), 15 I/O6 (io), 16 I/O7 (io), 17 GND (power), 18 TDO/IN1 (io), 19 I/O8 (io), 20 I/O9 (io), 21 I/O10 (io), 22 I/O11 (io), 23 I/O12 (io), 24 I/O13 (io), 25 I/O14 (io), 26 I/O15 (io), 27 TCK/Y2 (in), 28 VCC (power), 29 ~{RESET}/Y1 (in), 30 TMS/NC (in), 31 I/O16 (io), 32 I/O17 (io), 33 I/O18 (io), 34 I/O19 (io), 35 I/O20 (io), 36 I/O21 (io), 37 I/O22 (io), 38 I/O23 (io), 39 GND (power), 40 GOE0 (in), 41 I/O24 (io), 42 I/O25 (io), 43 I/O26 (io), 44 I/O27 (io)

## ispLSI2032V-60LT44I
designator U?
3.3V High-Density Programmable Logic
footprint TQFP44_N (Thin QFP, 44-Leads, Body 10x10mm, Pitch 0.8mm, IPC Medium Density)
footprint TQFP44_L (Thin QFP, 44-Leads, Body 10x10mm, Pitch 0.8mm, IPC High Density)
footprint TQFP44_M (Thin QFP, 44-Leads, Body 10x10mm, Pitch 0.8mm, IPC Low Density)
3D model 2032V-TQFP44 (44-Pin Thin Quad Flat Pack 0.8 mm Pitch)
pins: 1 I/O28 (io), 2 I/O29 (io), 3 I/O30 (io), 4 I/O31 (io), 5 Y0 (in), 6 VCC (power), 7 ~{ispEN} (in), 8 TDI/IN0 (in), 9 I/O0 (io), 10 I/O1 (io), 11 I/O2 (io), 12 I/O3 (io), 13 I/O4 (io), 14 I/O5 (io), 15 I/O6 (io), 16 I/O7 (io), 17 GND (power), 18 TDO/IN1 (io), 19 I/O8 (io), 20 I/O9 (io), 21 I/O10 (io), 22 I/O11 (io), 23 I/O12 (io), 24 I/O13 (io), 25 I/O14 (io), 26 I/O15 (io), 27 TCK/Y2 (in), 28 VCC (power), 29 ~{RESET}/Y1 (in), 30 TMS/NC (in), 31 I/O16 (io), 32 I/O17 (io), 33 I/O18 (io), 34 I/O19 (io), 35 I/O20 (io), 36 I/O21 (io), 37 I/O22 (io), 38 I/O23 (io), 39 GND (power), 40 GOE0 (in), 41 I/O24 (io), 42 I/O25 (io), 43 I/O26 (io), 44 I/O27 (io)

## ispLSI2032V-80LJ44
designator U?
3.3V High-Density Programmable Logic
footprint PLCC44_N (Leaded Chip Carrier, 44-Leads, Body 16.6x16.6mm, Pitch 1.27mm, IPC Medium Density)
footprint PLCC44_L (Leaded Chip Carrier, 44-Leads, Body 16.6x16.6mm, Pitch 1.27mm, IPC High Density)
footprint PLCC44_M (Leaded Chip Carrier, 44-Leads, Body 16.6x16.6mm, Pitch 1.27mm, IPC Low Density)
3D model 2032V-PLCC44 (44-Pin Leaded Chip Carrier 1.27 mm Pitch)
pins: 1 GND (power), 2 GOE0 (in), 3 I/O24 (io), 4 I/O25 (io), 5 I/O26 (io), 6 I/O27 (io), 7 I/O28 (io), 8 I/O29 (io), 9 I/O30 (io), 10 I/O31 (io), 11 Y0 (in), 12 VCC (power), 13 ~{ispEN} (in), 14 TDI/IN0 (in), 15 I/O0 (io), 16 I/O1 (io), 17 I/O2 (io), 18 I/O3 (io), 19 I/O4 (io), 20 I/O5 (io), 21 I/O6 (io), 22 I/O7 (io), 23 GND (power), 24 TDO/IN1 (io), 25 I/O8 (io), 26 I/O9 (io), 27 I/O10 (io), 28 I/O11 (io), 29 I/O12 (io), 30 I/O13 (io), 31 I/O14 (io), 32 I/O15 (io), 33 TCK/Y2 (in), 34 VCC (power), 35 ~{RESET}/Y1 (in), 36 TMS/NC (in), 37 I/O16 (io), 38 I/O17 (io), 39 I/O18 (io), 40 I/O19 (io), 41 I/O20 (io), 42 I/O21 (io), 43 I/O22 (io), 44 I/O23 (io)

## ispLSI2032V-80LT44
designator U?
3.3V High-Density Programmable Logic
footprint TQFP44_N (Thin QFP, 44-Leads, Body 10x10mm, Pitch 0.8mm, IPC Medium Density)
footprint TQFP44_L (Thin QFP, 44-Leads, Body 10x10mm, Pitch 0.8mm, IPC High Density)
footprint TQFP44_M (Thin QFP, 44-Leads, Body 10x10mm, Pitch 0.8mm, IPC Low Density)
3D model 2032V-TQFP44 (44-Pin Thin Quad Flat Pack 0.8 mm Pitch)
pins: 1 I/O28 (io), 2 I/O29 (io), 3 I/O30 (io), 4 I/O31 (io), 5 Y0 (in), 6 VCC (power), 7 ~{ispEN} (in), 8 TDI/IN0 (in), 9 I/O0 (io), 10 I/O1 (io), 11 I/O2 (io), 12 I/O3 (io), 13 I/O4 (io), 14 I/O5 (io), 15 I/O6 (io), 16 I/O7 (io), 17 GND (power), 18 TDO/IN1 (io), 19 I/O8 (io), 20 I/O9 (io), 21 I/O10 (io), 22 I/O11 (io), 23 I/O12 (io), 24 I/O13 (io), 25 I/O14 (io), 26 I/O15 (io), 27 TCK/Y2 (in), 28 VCC (power), 29 ~{RESET}/Y1 (in), 30 TMS/NC (in), 31 I/O16 (io), 32 I/O17 (io), 33 I/O18 (io), 34 I/O19 (io), 35 I/O20 (io), 36 I/O21 (io), 37 I/O22 (io), 38 I/O23 (io), 39 GND (power), 40 GOE0 (in), 41 I/O24 (io), 42 I/O25 (io), 43 I/O26 (io), 44 I/O27 (io)

## ispLSI2032V-100LJ44
designator U?
3.3V High-Density Programmable Logic
footprint PLCC44_N (Leaded Chip Carrier, 44-Leads, Body 16.6x16.6mm, Pitch 1.27mm, IPC Medium Density)
footprint PLCC44_L (Leaded Chip Carrier, 44-Leads, Body 16.6x16.6mm, Pitch 1.27mm, IPC High Density)
footprint PLCC44_M (Leaded Chip Carrier, 44-Leads, Body 16.6x16.6mm, Pitch 1.27mm, IPC Low Density)
3D model 2032V-PLCC44 (44-Pin Leaded Chip Carrier 1.27 mm Pitch)
pins: 1 GND (power), 2 GOE0 (in), 3 I/O24 (io), 4 I/O25 (io), 5 I/O26 (io), 6 I/O27 (io), 7 I/O28 (io), 8 I/O29 (io), 9 I/O30 (io), 10 I/O31 (io), 11 Y0 (in), 12 VCC (power), 13 ~{ispEN} (in), 14 TDI/IN0 (in), 15 I/O0 (io), 16 I/O1 (io), 17 I/O2 (io), 18 I/O3 (io), 19 I/O4 (io), 20 I/O5 (io), 21 I/O6 (io), 22 I/O7 (io), 23 GND (power), 24 TDO/IN1 (io), 25 I/O8 (io), 26 I/O9 (io), 27 I/O10 (io), 28 I/O11 (io), 29 I/O12 (io), 30 I/O13 (io), 31 I/O14 (io), 32 I/O15 (io), 33 TCK/Y2 (in), 34 VCC (power), 35 ~{RESET}/Y1 (in), 36 TMS/NC (in), 37 I/O16 (io), 38 I/O17 (io), 39 I/O18 (io), 40 I/O19 (io), 41 I/O20 (io), 42 I/O21 (io), 43 I/O22 (io), 44 I/O23 (io)

## ispLSI2032V-100LT44
designator U?
3.3V High-Density Programmable Logic
footprint TQFP44_N (Thin QFP, 44-Leads, Body 10x10mm, Pitch 0.8mm, IPC Medium Density)
footprint TQFP44_L (Thin QFP, 44-Leads, Body 10x10mm, Pitch 0.8mm, IPC High Density)
footprint TQFP44_M (Thin QFP, 44-Leads, Body 10x10mm, Pitch 0.8mm, IPC Low Density)
3D model 2032V-TQFP44 (44-Pin Thin Quad Flat Pack 0.8 mm Pitch)
pins: 1 I/O28 (io), 2 I/O29 (io), 3 I/O30 (io), 4 I/O31 (io), 5 Y0 (in), 6 VCC (power), 7 ~{ispEN} (in), 8 TDI/IN0 (in), 9 I/O0 (io), 10 I/O1 (io), 11 I/O2 (io), 12 I/O3 (io), 13 I/O4 (io), 14 I/O5 (io), 15 I/O6 (io), 16 I/O7 (io), 17 GND (power), 18 TDO/IN1 (io), 19 I/O8 (io), 20 I/O9 (io), 21 I/O10 (io), 22 I/O11 (io), 23 I/O12 (io), 24 I/O13 (io), 25 I/O14 (io), 26 I/O15 (io), 27 TCK/Y2 (in), 28 VCC (power), 29 ~{RESET}/Y1 (in), 30 TMS/NC (in), 31 I/O16 (io), 32 I/O17 (io), 33 I/O18 (io), 34 I/O19 (io), 35 I/O20 (io), 36 I/O21 (io), 37 I/O22 (io), 38 I/O23 (io), 39 GND (power), 40 GOE0 (in), 41 I/O24 (io), 42 I/O25 (io), 43 I/O26 (io), 44 I/O27 (io)

## ispLSI2032VE-110LB49
designator U?
3.3V In-System Programmable High Density SuperFAST PLD
footprint caBGA49 (BGA, 49-Leads, Body 7x7mm, Pitch 0.8mm)
3D model 2032VE-caBGA49 (49-Ball Chip Array Ball Grid Array (caBGA49))
pins: A1 NC, A2 I/O27 (io), A3 I/O25 (io), A4 GOE0 (in), A5 I/O23 (io), A6 I/O21 (io), A7 NC, B1 I/O30 (io), B2 I/O26 (io), B3 I/O24 (io), B4 I/O22 (io), B5 I/O20 (io), B6 I/O17 (io), B7 I/O18 (io), C1 Y0 (in), C2 I/O29 (io), C3 I/O28 (io), C4 GND (power), C5 I/O19 (io), C6 TMS/NC (in), C7 I/O16 (io), D1 ~{BSCAN} (in), D2 I/O31 (io), D3 VCC (power), D4 NC, D5 VCC (power), D6 I/O15 (io), D7 ~{RESET} /Y1 (in), E1 I/O0 (io), E2 TDI/IN0 (in), E3 I/O3 (io), E4 GND (power), E5 I/O12 (io), E6 I/O13 (io), E7 TCK/Y2 (in), F1 I/O2 (io), F2 I/O1 (io), F3 I/O4 (io), F4 I/O6 (io), F5 I/O8 (io), F6 I/O10 (io), F7 I/O14 (io), G1 NC, G2 I/O5 (io), G3 I/O7 (io), G4 TDO/IN1 (io), G5 I/O9 (io), G6 I/O11 (io), G7 NC

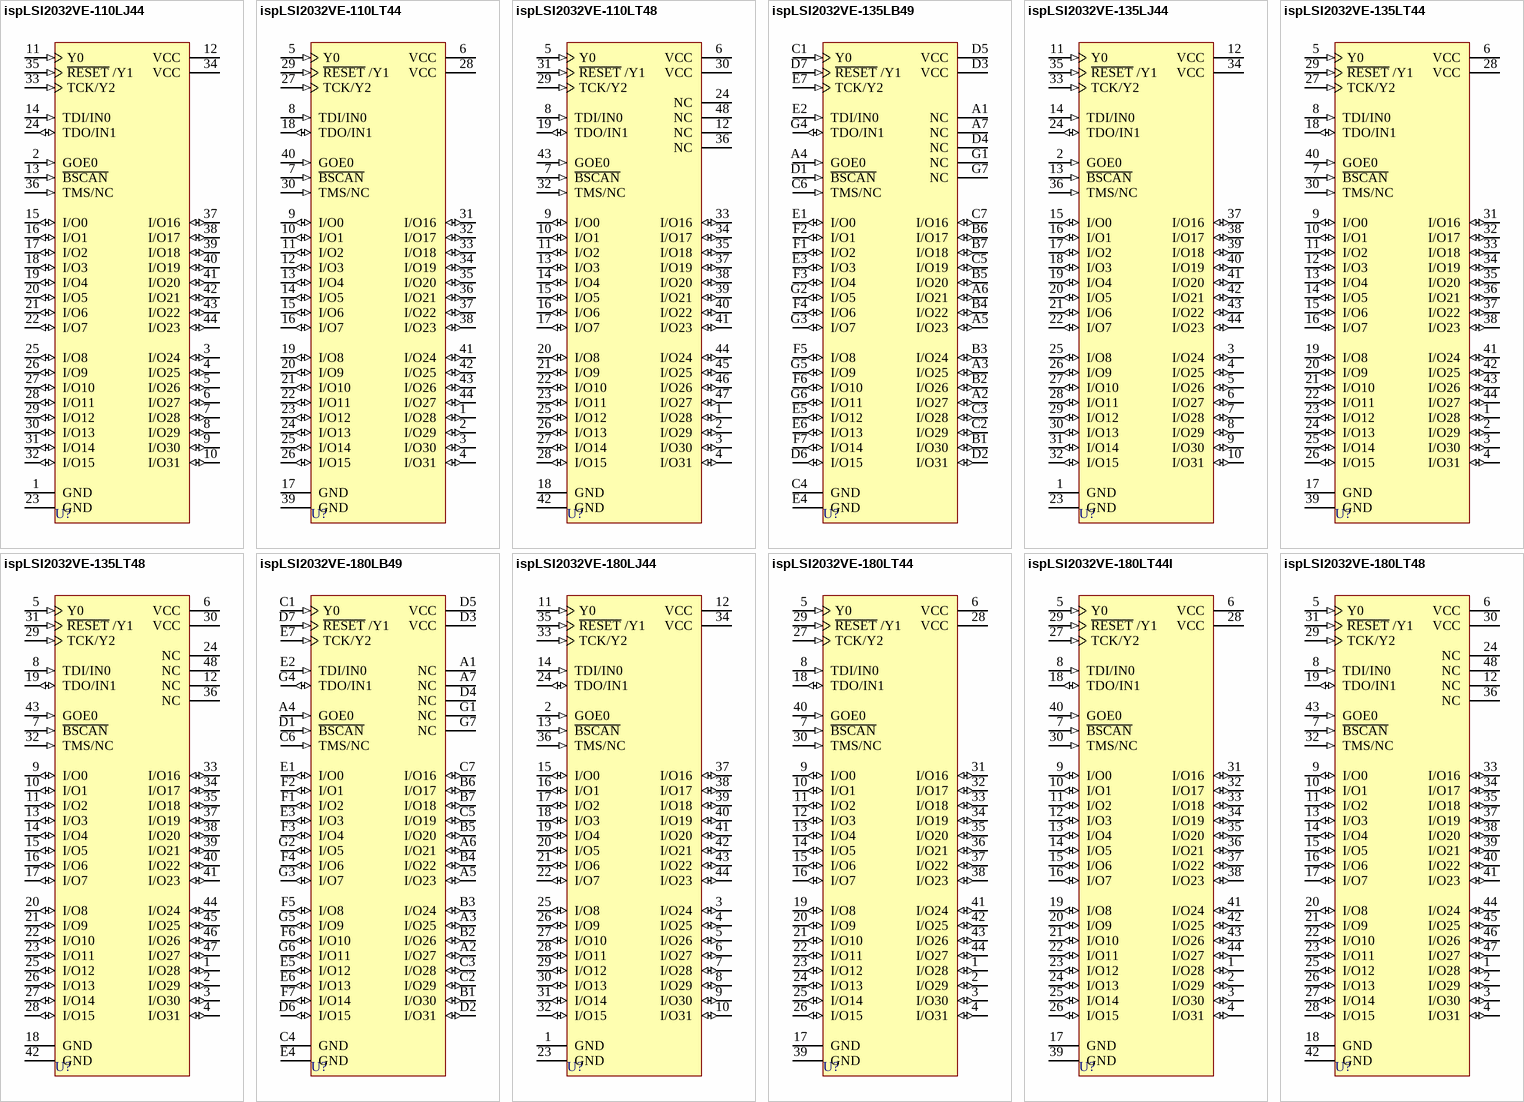
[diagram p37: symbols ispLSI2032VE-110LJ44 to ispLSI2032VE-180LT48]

## ispLSI2032VE-110LJ44
designator U?
3.3V In-System Programmable High Density SuperFAST PLD
footprint PLCC44_N (Leaded Chip Carrier, 44-Leads, Body 16.6x16.6mm, Pitch 1.27mm, IPC Medium Density)
footprint PLCC44_L (Leaded Chip Carrier, 44-Leads, Body 16.6x16.6mm, Pitch 1.27mm, IPC High Density)
footprint PLCC44_M (Leaded Chip Carrier, 44-Leads, Body 16.6x16.6mm, Pitch 1.27mm, IPC Low Density)
3D model 2032VE-PLCC44 (44-Pin Leaded Chip Carrier 1.27 mm Pitch)
pins: 1 GND (power), 2 GOE0 (in), 3 I/O24 (io), 4 I/O25 (io), 5 I/O26 (io), 6 I/O27 (io), 7 I/O28 (io), 8 I/O29 (io), 9 I/O30 (io), 10 I/O31 (io), 11 Y0 (in), 12 VCC (power), 13 ~{BSCAN} (in), 14 TDI/IN0 (in), 15 I/O0 (io), 16 I/O1 (io), 17 I/O2 (io), 18 I/O3 (io), 19 I/O4 (io), 20 I/O5 (io), 21 I/O6 (io), 22 I/O7 (io), 23 GND (power), 24 TDO/IN1 (io), 25 I/O8 (io), 26 I/O9 (io), 27 I/O10 (io), 28 I/O11 (io), 29 I/O12 (io), 30 I/O13 (io), 31 I/O14 (io), 32 I/O15 (io), 33 TCK/Y2 (in), 34 VCC (power), 35 ~{RESET} /Y1 (in), 36 TMS/NC (in), 37 I/O16 (io), 38 I/O17 (io), 39 I/O18 (io), 40 I/O19 (io), 41 I/O20 (io), 42 I/O21 (io), 43 I/O22 (io), 44 I/O23 (io)

## ispLSI2032VE-110LT44
designator U?
3.3V In-System Programmable High Density SuperFAST PLD
footprint TQFP44_N (Thin QFP, 44-Leads, Body 10x10mm, Pitch 0.8mm, IPC Medium Density)
footprint TQFP44_L (Thin QFP, 44-Leads, Body 10x10mm, Pitch 0.8mm, IPC High Density)
footprint TQFP44_M (Thin QFP, 44-Leads, Body 10x10mm, Pitch 0.8mm, IPC Low Density)
3D model 2032VE-TQFP44 (44-Pin Thin Quad Flat Pack 0.8 mm Pitch)
pins: 1 I/O28 (io), 2 I/O29 (io), 3 I/O30 (io), 4 I/O31 (io), 5 Y0 (in), 6 VCC (power), 7 ~{BSCAN} (in), 8 TDI/IN0 (in), 9 I/O0 (io), 10 I/O1 (io), 11 I/O2 (io), 12 I/O3 (io), 13 I/O4 (io), 14 I/O5 (io), 15 I/O6 (io), 16 I/O7 (io), 17 GND (power), 18 TDO/IN1 (io), 19 I/O8 (io), 20 I/O9 (io), 21 I/O10 (io), 22 I/O11 (io), 23 I/O12 (io), 24 I/O13 (io), 25 I/O14 (io), 26 I/O15 (io), 27 TCK/Y2 (in), 28 VCC (power), 29 ~{RESET} /Y1 (in), 30 TMS/NC (in), 31 I/O16 (io), 32 I/O17 (io), 33 I/O18 (io), 34 I/O19 (io), 35 I/O20 (io), 36 I/O21 (io), 37 I/O22 (io), 38 I/O23 (io), 39 GND (power), 40 GOE0 (in), 41 I/O24 (io), 42 I/O25 (io), 43 I/O26 (io), 44 I/O27 (io)

## ispLSI2032VE-110LT48
designator U?
3.3V In-System Programmable High Density SuperFAST PLD
footprint TQFP48_N (Thin QFP, 48-Leads, Body 7x7mm, Pitch 0.5mm, IPC Medium Density)
footprint TQFP48_L (Thin QFP, 48-Leads, Body 7x7mm, Pitch 0.5mm, IPC High Density)
footprint TQFP48_M (Thin QFP, 48-Leads, Body 7x7mm, Pitch 0.5mm, IPC Low Density)
3D model 2032VE-TQFP48 (48-Pin Thin Quad Flat Pack 0.5 mm Pitch)
pins: 1 I/O28 (io), 2 I/O29 (io), 3 I/O30 (io), 4 I/O31 (io), 5 Y0 (in), 6 VCC (power), 7 ~{BSCAN} (in), 8 TDI/IN0 (in), 9 I/O0 (io), 10 I/O1 (io), 11 I/O2 (io), 12 NC, 13 I/O3 (io), 14 I/O4 (io), 15 I/O5 (io), 16 I/O6 (io), 17 I/O7 (io), 18 GND (power), 19 TDO/IN1 (io), 20 I/O8 (io), 21 I/O9 (io), 22 I/O10 (io), 23 I/O11 (io), 24 NC, 25 I/O12 (io), 26 I/O13 (io), 27 I/O14 (io), 28 I/O15 (io), 29 TCK/Y2 (in), 30 VCC (power), 31 ~{RESET} /Y1 (in), 32 TMS/NC (in), 33 I/O16 (io), 34 I/O17 (io), 35 I/O18 (io), 36 NC, 37 I/O19 (io), 38 I/O20 (io), 39 I/O21 (io), 40 I/O22 (io), 41 I/O23 (io), 42 GND (power), 43 GOE0 (in), 44 I/O24 (io), 45 I/O25 (io), 46 I/O26 (io), 47 I/O27 (io), 48 NC

## ispLSI2032VE-135LB49
designator U?
3.3V In-System Programmable High Density SuperFAST PLD
footprint caBGA49 (BGA, 49-Leads, Body 7x7mm, Pitch 0.8mm)
3D model 2032VE-caBGA49 (49-Ball Chip Array Ball Grid Array (caBGA49))
pins: A1 NC, A2 I/O27 (io), A3 I/O25 (io), A4 GOE0 (in), A5 I/O23 (io), A6 I/O21 (io), A7 NC, B1 I/O30 (io), B2 I/O26 (io), B3 I/O24 (io), B4 I/O22 (io), B5 I/O20 (io), B6 I/O17 (io), B7 I/O18 (io), C1 Y0 (in), C2 I/O29 (io), C3 I/O28 (io), C4 GND (power), C5 I/O19 (io), C6 TMS/NC (in), C7 I/O16 (io), D1 ~{BSCAN} (in), D2 I/O31 (io), D3 VCC (power), D4 NC, D5 VCC (power), D6 I/O15 (io), D7 ~{RESET} /Y1 (in), E1 I/O0 (io), E2 TDI/IN0 (in), E3 I/O3 (io), E4 GND (power), E5 I/O12 (io), E6 I/O13 (io), E7 TCK/Y2 (in), F1 I/O2 (io), F2 I/O1 (io), F3 I/O4 (io), F4 I/O6 (io), F5 I/O8 (io), F6 I/O10 (io), F7 I/O14 (io), G1 NC, G2 I/O5 (io), G3 I/O7 (io), G4 TDO/IN1 (io), G5 I/O9 (io), G6 I/O11 (io), G7 NC

## ispLSI2032VE-135LJ44
designator U?
3.3V In-System Programmable High Density SuperFAST PLD
footprint PLCC44_N (Leaded Chip Carrier, 44-Leads, Body 16.6x16.6mm, Pitch 1.27mm, IPC Medium Density)
footprint PLCC44_L (Leaded Chip Carrier, 44-Leads, Body 16.6x16.6mm, Pitch 1.27mm, IPC High Density)
footprint PLCC44_M (Leaded Chip Carrier, 44-Leads, Body 16.6x16.6mm, Pitch 1.27mm, IPC Low Density)
3D model 2032VE-PLCC44 (44-Pin Leaded Chip Carrier 1.27 mm Pitch)
pins: 1 GND (power), 2 GOE0 (in), 3 I/O24 (io), 4 I/O25 (io), 5 I/O26 (io), 6 I/O27 (io), 7 I/O28 (io), 8 I/O29 (io), 9 I/O30 (io), 10 I/O31 (io), 11 Y0 (in), 12 VCC (power), 13 ~{BSCAN} (in), 14 TDI/IN0 (in), 15 I/O0 (io), 16 I/O1 (io), 17 I/O2 (io), 18 I/O3 (io), 19 I/O4 (io), 20 I/O5 (io), 21 I/O6 (io), 22 I/O7 (io), 23 GND (power), 24 TDO/IN1 (io), 25 I/O8 (io), 26 I/O9 (io), 27 I/O10 (io), 28 I/O11 (io), 29 I/O12 (io), 30 I/O13 (io), 31 I/O14 (io), 32 I/O15 (io), 33 TCK/Y2 (in), 34 VCC (power), 35 ~{RESET} /Y1 (in), 36 TMS/NC (in), 37 I/O16 (io), 38 I/O17 (io), 39 I/O18 (io), 40 I/O19 (io), 41 I/O20 (io), 42 I/O21 (io), 43 I/O22 (io), 44 I/O23 (io)

## ispLSI2032VE-135LT44
designator U?
3.3V In-System Programmable High Density SuperFAST PLD
footprint TQFP44_N (Thin QFP, 44-Leads, Body 10x10mm, Pitch 0.8mm, IPC Medium Density)
footprint TQFP44_L (Thin QFP, 44-Leads, Body 10x10mm, Pitch 0.8mm, IPC High Density)
footprint TQFP44_M (Thin QFP, 44-Leads, Body 10x10mm, Pitch 0.8mm, IPC Low Density)
3D model 2032VE-TQFP44 (44-Pin Thin Quad Flat Pack 0.8 mm Pitch)
pins: 1 I/O28 (io), 2 I/O29 (io), 3 I/O30 (io), 4 I/O31 (io), 5 Y0 (in), 6 VCC (power), 7 ~{BSCAN} (in), 8 TDI/IN0 (in), 9 I/O0 (io), 10 I/O1 (io), 11 I/O2 (io), 12 I/O3 (io), 13 I/O4 (io), 14 I/O5 (io), 15 I/O6 (io), 16 I/O7 (io), 17 GND (power), 18 TDO/IN1 (io), 19 I/O8 (io), 20 I/O9 (io), 21 I/O10 (io), 22 I/O11 (io), 23 I/O12 (io), 24 I/O13 (io), 25 I/O14 (io), 26 I/O15 (io), 27 TCK/Y2 (in), 28 VCC (power), 29 ~{RESET} /Y1 (in), 30 TMS/NC (in), 31 I/O16 (io), 32 I/O17 (io), 33 I/O18 (io), 34 I/O19 (io), 35 I/O20 (io), 36 I/O21 (io), 37 I/O22 (io), 38 I/O23 (io), 39 GND (power), 40 GOE0 (in), 41 I/O24 (io), 42 I/O25 (io), 43 I/O26 (io), 44 I/O27 (io)

## ispLSI2032VE-135LT48
designator U?
3.3V In-System Programmable High Density SuperFAST PLD
footprint TQFP48_N (Thin QFP, 48-Leads, Body 7x7mm, Pitch 0.5mm, IPC Medium Density)
footprint TQFP48_L (Thin QFP, 48-Leads, Body 7x7mm, Pitch 0.5mm, IPC High Density)
footprint TQFP48_M (Thin QFP, 48-Leads, Body 7x7mm, Pitch 0.5mm, IPC Low Density)
3D model 2032VE-TQFP48 (48-Pin Thin Quad Flat Pack 0.5 mm Pitch)
pins: 1 I/O28 (io), 2 I/O29 (io), 3 I/O30 (io), 4 I/O31 (io), 5 Y0 (in), 6 VCC (power), 7 ~{BSCAN} (in), 8 TDI/IN0 (in), 9 I/O0 (io), 10 I/O1 (io), 11 I/O2 (io), 12 NC, 13 I/O3 (io), 14 I/O4 (io), 15 I/O5 (io), 16 I/O6 (io), 17 I/O7 (io), 18 GND (power), 19 TDO/IN1 (io), 20 I/O8 (io), 21 I/O9 (io), 22 I/O10 (io), 23 I/O11 (io), 24 NC, 25 I/O12 (io), 26 I/O13 (io), 27 I/O14 (io), 28 I/O15 (io), 29 TCK/Y2 (in), 30 VCC (power), 31 ~{RESET} /Y1 (in), 32 TMS/NC (in), 33 I/O16 (io), 34 I/O17 (io), 35 I/O18 (io), 36 NC, 37 I/O19 (io), 38 I/O20 (io), 39 I/O21 (io), 40 I/O22 (io), 41 I/O23 (io), 42 GND (power), 43 GOE0 (in), 44 I/O24 (io), 45 I/O25 (io), 46 I/O26 (io), 47 I/O27 (io), 48 NC

## ispLSI2032VE-180LB49
designator U?
3.3V In-System Programmable High Density SuperFAST PLD
footprint caBGA49 (BGA, 49-Leads, Body 7x7mm, Pitch 0.8mm)
3D model 2032VE-caBGA49 (49-Ball Chip Array Ball Grid Array (caBGA49))
pins: A1 NC, A2 I/O27 (io), A3 I/O25 (io), A4 GOE0 (in), A5 I/O23 (io), A6 I/O21 (io), A7 NC, B1 I/O30 (io), B2 I/O26 (io), B3 I/O24 (io), B4 I/O22 (io), B5 I/O20 (io), B6 I/O17 (io), B7 I/O18 (io), C1 Y0 (in), C2 I/O29 (io), C3 I/O28 (io), C4 GND (power), C5 I/O19 (io), C6 TMS/NC (in), C7 I/O16 (io), D1 ~{BSCAN} (in), D2 I/O31 (io), D3 VCC (power), D4 NC, D5 VCC (power), D6 I/O15 (io), D7 ~{RESET} /Y1 (in), E1 I/O0 (io), E2 TDI/IN0 (in), E3 I/O3 (io), E4 GND (power), E5 I/O12 (io), E6 I/O13 (io), E7 TCK/Y2 (in), F1 I/O2 (io), F2 I/O1 (io), F3 I/O4 (io), F4 I/O6 (io), F5 I/O8 (io), F6 I/O10 (io), F7 I/O14 (io), G1 NC, G2 I/O5 (io), G3 I/O7 (io), G4 TDO/IN1 (io), G5 I/O9 (io), G6 I/O11 (io), G7 NC

## ispLSI2032VE-180LJ44
designator U?
3.3V In-System Programmable High Density SuperFAST PLD
footprint PLCC44_N (Leaded Chip Carrier, 44-Leads, Body 16.6x16.6mm, Pitch 1.27mm, IPC Medium Density)
footprint PLCC44_L (Leaded Chip Carrier, 44-Leads, Body 16.6x16.6mm, Pitch 1.27mm, IPC High Density)
footprint PLCC44_M (Leaded Chip Carrier, 44-Leads, Body 16.6x16.6mm, Pitch 1.27mm, IPC Low Density)
3D model 2032VE-PLCC44 (44-Pin Leaded Chip Carrier 1.27 mm Pitch)
pins: 1 GND (power), 2 GOE0 (in), 3 I/O24 (io), 4 I/O25 (io), 5 I/O26 (io), 6 I/O27 (io), 7 I/O28 (io), 8 I/O29 (io), 9 I/O30 (io), 10 I/O31 (io), 11 Y0 (in), 12 VCC (power), 13 ~{BSCAN} (in), 14 TDI/IN0 (in), 15 I/O0 (io), 16 I/O1 (io), 17 I/O2 (io), 18 I/O3 (io), 19 I/O4 (io), 20 I/O5 (io), 21 I/O6 (io), 22 I/O7 (io), 23 GND (power), 24 TDO/IN1 (io), 25 I/O8 (io), 26 I/O9 (io), 27 I/O10 (io), 28 I/O11 (io), 29 I/O12 (io), 30 I/O13 (io), 31 I/O14 (io), 32 I/O15 (io), 33 TCK/Y2 (in), 34 VCC (power), 35 ~{RESET} /Y1 (in), 36 TMS/NC (in), 37 I/O16 (io), 38 I/O17 (io), 39 I/O18 (io), 40 I/O19 (io), 41 I/O20 (io), 42 I/O21 (io), 43 I/O22 (io), 44 I/O23 (io)

## ispLSI2032VE-180LT44
designator U?
3.3V In-System Programmable High Density SuperFAST PLD
footprint TQFP44_N (Thin QFP, 44-Leads, Body 10x10mm, Pitch 0.8mm, IPC Medium Density)
footprint TQFP44_L (Thin QFP, 44-Leads, Body 10x10mm, Pitch 0.8mm, IPC High Density)
footprint TQFP44_M (Thin QFP, 44-Leads, Body 10x10mm, Pitch 0.8mm, IPC Low Density)
3D model 2032VE-TQFP44 (44-Pin Thin Quad Flat Pack 0.8 mm Pitch)
pins: 1 I/O28 (io), 2 I/O29 (io), 3 I/O30 (io), 4 I/O31 (io), 5 Y0 (in), 6 VCC (power), 7 ~{BSCAN} (in), 8 TDI/IN0 (in), 9 I/O0 (io), 10 I/O1 (io), 11 I/O2 (io), 12 I/O3 (io), 13 I/O4 (io), 14 I/O5 (io), 15 I/O6 (io), 16 I/O7 (io), 17 GND (power), 18 TDO/IN1 (io), 19 I/O8 (io), 20 I/O9 (io), 21 I/O10 (io), 22 I/O11 (io), 23 I/O12 (io), 24 I/O13 (io), 25 I/O14 (io), 26 I/O15 (io), 27 TCK/Y2 (in), 28 VCC (power), 29 ~{RESET} /Y1 (in), 30 TMS/NC (in), 31 I/O16 (io), 32 I/O17 (io), 33 I/O18 (io), 34 I/O19 (io), 35 I/O20 (io), 36 I/O21 (io), 37 I/O22 (io), 38 I/O23 (io), 39 GND (power), 40 GOE0 (in), 41 I/O24 (io), 42 I/O25 (io), 43 I/O26 (io), 44 I/O27 (io)

## ispLSI2032VE-180LT44I
designator U?
3.3V In-System Programmable High Density SuperFAST PLD
footprint TQFP44_N (Thin QFP, 44-Leads, Body 10x10mm, Pitch 0.8mm, IPC Medium Density)
footprint TQFP44_L (Thin QFP, 44-Leads, Body 10x10mm, Pitch 0.8mm, IPC High Density)
footprint TQFP44_M (Thin QFP, 44-Leads, Body 10x10mm, Pitch 0.8mm, IPC Low Density)
3D model 2032VE-TQFP44 (44-Pin Thin Quad Flat Pack 0.8 mm Pitch)
pins: 1 I/O28 (io), 2 I/O29 (io), 3 I/O30 (io), 4 I/O31 (io), 5 Y0 (in), 6 VCC (power), 7 ~{BSCAN} (in), 8 TDI/IN0 (in), 9 I/O0 (io), 10 I/O1 (io), 11 I/O2 (io), 12 I/O3 (io), 13 I/O4 (io), 14 I/O5 (io), 15 I/O6 (io), 16 I/O7 (io), 17 GND (power), 18 TDO/IN1 (io), 19 I/O8 (io), 20 I/O9 (io), 21 I/O10 (io), 22 I/O11 (io), 23 I/O12 (io), 24 I/O13 (io), 25 I/O14 (io), 26 I/O15 (io), 27 TCK/Y2 (in), 28 VCC (power), 29 ~{RESET} /Y1 (in), 30 TMS/NC (in), 31 I/O16 (io), 32 I/O17 (io), 33 I/O18 (io), 34 I/O19 (io), 35 I/O20 (io), 36 I/O21 (io), 37 I/O22 (io), 38 I/O23 (io), 39 GND (power), 40 GOE0 (in), 41 I/O24 (io), 42 I/O25 (io), 43 I/O26 (io), 44 I/O27 (io)

## ispLSI2032VE-180LT48
designator U?
3.3V In-System Programmable High Density SuperFAST PLD
footprint TQFP48_N (Thin QFP, 48-Leads, Body 7x7mm, Pitch 0.5mm, IPC Medium Density)
footprint TQFP48_L (Thin QFP, 48-Leads, Body 7x7mm, Pitch 0.5mm, IPC High Density)
footprint TQFP48_M (Thin QFP, 48-Leads, Body 7x7mm, Pitch 0.5mm, IPC Low Density)
3D model 2032VE-TQFP48 (48-Pin Thin Quad Flat Pack 0.5 mm Pitch)
pins: 1 I/O28 (io), 2 I/O29 (io), 3 I/O30 (io), 4 I/O31 (io), 5 Y0 (in), 6 VCC (power), 7 ~{BSCAN} (in), 8 TDI/IN0 (in), 9 I/O0 (io), 10 I/O1 (io), 11 I/O2 (io), 12 NC, 13 I/O3 (io), 14 I/O4 (io), 15 I/O5 (io), 16 I/O6 (io), 17 I/O7 (io), 18 GND (power), 19 TDO/IN1 (io), 20 I/O8 (io), 21 I/O9 (io), 22 I/O10 (io), 23 I/O11 (io), 24 NC, 25 I/O12 (io), 26 I/O13 (io), 27 I/O14 (io), 28 I/O15 (io), 29 TCK/Y2 (in), 30 VCC (power), 31 ~{RESET} /Y1 (in), 32 TMS/NC (in), 33 I/O16 (io), 34 I/O17 (io), 35 I/O18 (io), 36 NC, 37 I/O19 (io), 38 I/O20 (io), 39 I/O21 (io), 40 I/O22 (io), 41 I/O23 (io), 42 GND (power), 43 GOE0 (in), 44 I/O24 (io), 45 I/O25 (io), 46 I/O26 (io), 47 I/O27 (io), 48 NC

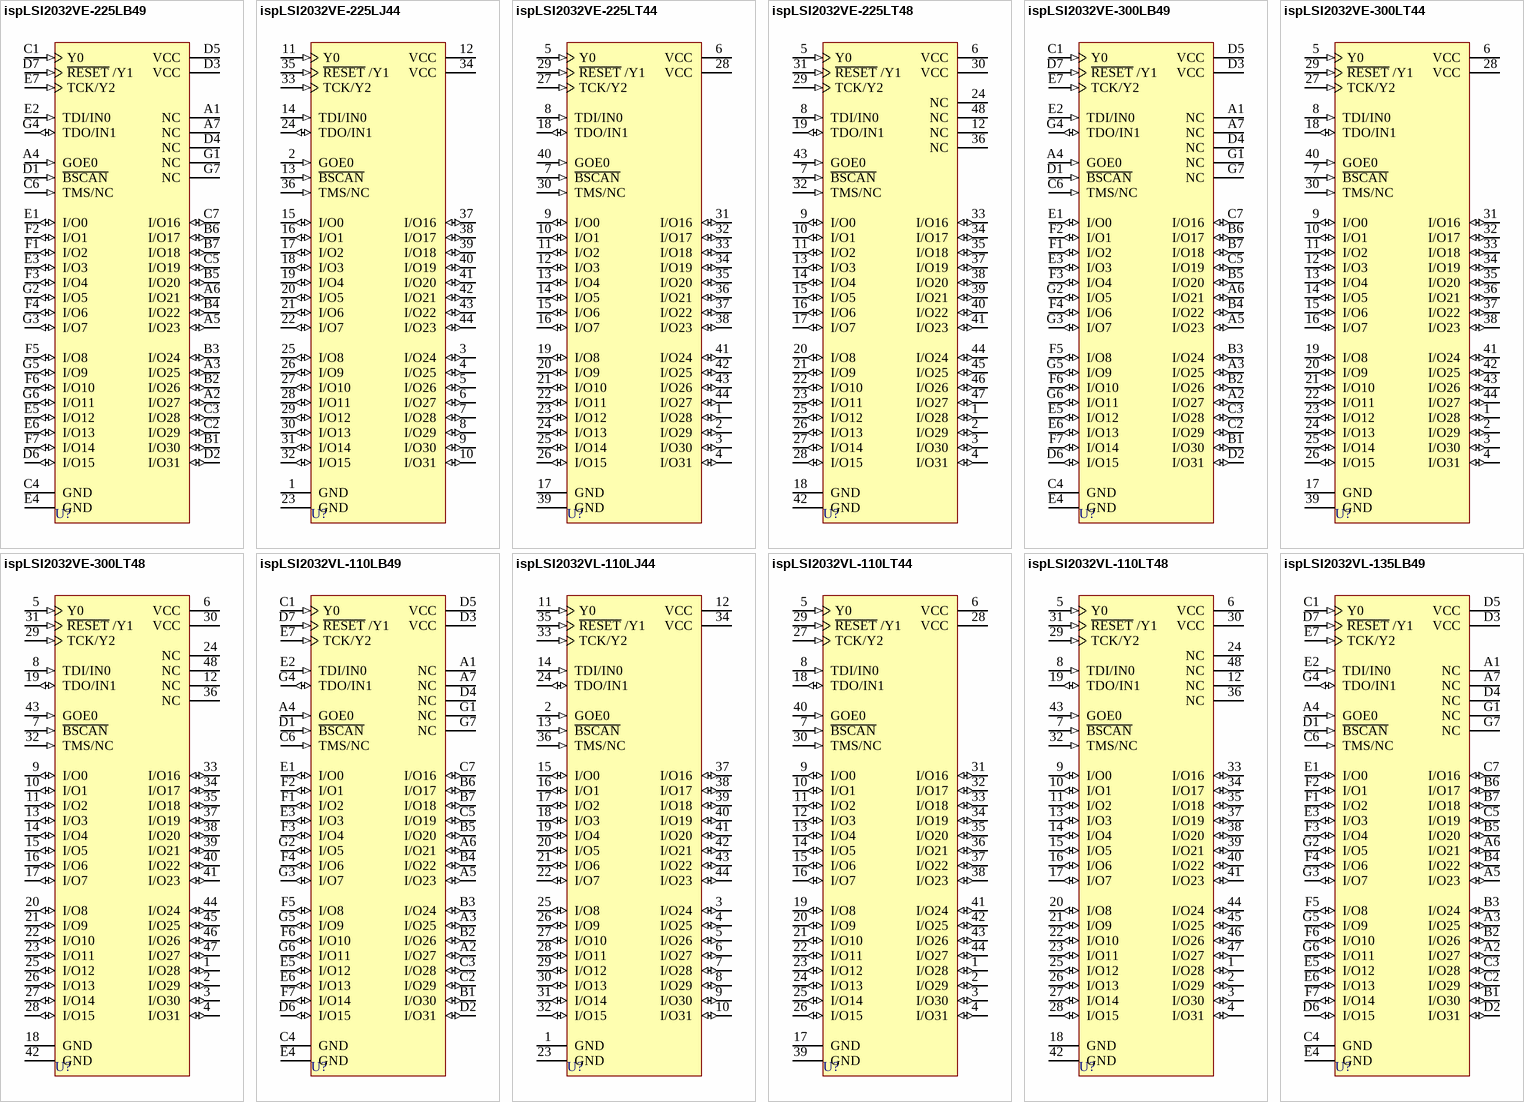
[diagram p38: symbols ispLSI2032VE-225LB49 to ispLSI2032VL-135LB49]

## ispLSI2032VE-225LB49
designator U?
3.3V In-System Programmable High Density SuperFAST PLD
footprint caBGA49 (BGA, 49-Leads, Body 7x7mm, Pitch 0.8mm)
3D model 2032VE-caBGA49 (49-Ball Chip Array Ball Grid Array (caBGA49))
pins: A1 NC, A2 I/O27 (io), A3 I/O25 (io), A4 GOE0 (in), A5 I/O23 (io), A6 I/O21 (io), A7 NC, B1 I/O30 (io), B2 I/O26 (io), B3 I/O24 (io), B4 I/O22 (io), B5 I/O20 (io), B6 I/O17 (io), B7 I/O18 (io), C1 Y0 (in), C2 I/O29 (io), C3 I/O28 (io), C4 GND (power), C5 I/O19 (io), C6 TMS/NC (in), C7 I/O16 (io), D1 ~{BSCAN} (in), D2 I/O31 (io), D3 VCC (power), D4 NC, D5 VCC (power), D6 I/O15 (io), D7 ~{RESET} /Y1 (in), E1 I/O0 (io), E2 TDI/IN0 (in), E3 I/O3 (io), E4 GND (power), E5 I/O12 (io), E6 I/O13 (io), E7 TCK/Y2 (in), F1 I/O2 (io), F2 I/O1 (io), F3 I/O4 (io), F4 I/O6 (io), F5 I/O8 (io), F6 I/O10 (io), F7 I/O14 (io), G1 NC, G2 I/O5 (io), G3 I/O7 (io), G4 TDO/IN1 (io), G5 I/O9 (io), G6 I/O11 (io), G7 NC

## ispLSI2032VE-225LJ44
designator U?
3.3V In-System Programmable High Density SuperFAST PLD
footprint PLCC44_N (Leaded Chip Carrier, 44-Leads, Body 16.6x16.6mm, Pitch 1.27mm, IPC Medium Density)
footprint PLCC44_L (Leaded Chip Carrier, 44-Leads, Body 16.6x16.6mm, Pitch 1.27mm, IPC High Density)
footprint PLCC44_M (Leaded Chip Carrier, 44-Leads, Body 16.6x16.6mm, Pitch 1.27mm, IPC Low Density)
3D model 2032VE-PLCC44 (44-Pin Leaded Chip Carrier 1.27 mm Pitch)
pins: 1 GND (power), 2 GOE0 (in), 3 I/O24 (io), 4 I/O25 (io), 5 I/O26 (io), 6 I/O27 (io), 7 I/O28 (io), 8 I/O29 (io), 9 I/O30 (io), 10 I/O31 (io), 11 Y0 (in), 12 VCC (power), 13 ~{BSCAN} (in), 14 TDI/IN0 (in), 15 I/O0 (io), 16 I/O1 (io), 17 I/O2 (io), 18 I/O3 (io), 19 I/O4 (io), 20 I/O5 (io), 21 I/O6 (io), 22 I/O7 (io), 23 GND (power), 24 TDO/IN1 (io), 25 I/O8 (io), 26 I/O9 (io), 27 I/O10 (io), 28 I/O11 (io), 29 I/O12 (io), 30 I/O13 (io), 31 I/O14 (io), 32 I/O15 (io), 33 TCK/Y2 (in), 34 VCC (power), 35 ~{RESET} /Y1 (in), 36 TMS/NC (in), 37 I/O16 (io), 38 I/O17 (io), 39 I/O18 (io), 40 I/O19 (io), 41 I/O20 (io), 42 I/O21 (io), 43 I/O22 (io), 44 I/O23 (io)

## ispLSI2032VE-225LT44
designator U?
3.3V In-System Programmable High Density SuperFAST PLD
footprint TQFP44_N (Thin QFP, 44-Leads, Body 10x10mm, Pitch 0.8mm, IPC Medium Density)
footprint TQFP44_L (Thin QFP, 44-Leads, Body 10x10mm, Pitch 0.8mm, IPC High Density)
footprint TQFP44_M (Thin QFP, 44-Leads, Body 10x10mm, Pitch 0.8mm, IPC Low Density)
3D model 2032VE-TQFP44 (44-Pin Thin Quad Flat Pack 0.8 mm Pitch)
pins: 1 I/O28 (io), 2 I/O29 (io), 3 I/O30 (io), 4 I/O31 (io), 5 Y0 (in), 6 VCC (power), 7 ~{BSCAN} (in), 8 TDI/IN0 (in), 9 I/O0 (io), 10 I/O1 (io), 11 I/O2 (io), 12 I/O3 (io), 13 I/O4 (io), 14 I/O5 (io), 15 I/O6 (io), 16 I/O7 (io), 17 GND (power), 18 TDO/IN1 (io), 19 I/O8 (io), 20 I/O9 (io), 21 I/O10 (io), 22 I/O11 (io), 23 I/O12 (io), 24 I/O13 (io), 25 I/O14 (io), 26 I/O15 (io), 27 TCK/Y2 (in), 28 VCC (power), 29 ~{RESET} /Y1 (in), 30 TMS/NC (in), 31 I/O16 (io), 32 I/O17 (io), 33 I/O18 (io), 34 I/O19 (io), 35 I/O20 (io), 36 I/O21 (io), 37 I/O22 (io), 38 I/O23 (io), 39 GND (power), 40 GOE0 (in), 41 I/O24 (io), 42 I/O25 (io), 43 I/O26 (io), 44 I/O27 (io)

## ispLSI2032VE-225LT48
designator U?
3.3V In-System Programmable High Density SuperFAST PLD
footprint TQFP48_N (Thin QFP, 48-Leads, Body 7x7mm, Pitch 0.5mm, IPC Medium Density)
footprint TQFP48_L (Thin QFP, 48-Leads, Body 7x7mm, Pitch 0.5mm, IPC High Density)
footprint TQFP48_M (Thin QFP, 48-Leads, Body 7x7mm, Pitch 0.5mm, IPC Low Density)
3D model 2032VE-TQFP48 (48-Pin Thin Quad Flat Pack 0.5 mm Pitch)
pins: 1 I/O28 (io), 2 I/O29 (io), 3 I/O30 (io), 4 I/O31 (io), 5 Y0 (in), 6 VCC (power), 7 ~{BSCAN} (in), 8 TDI/IN0 (in), 9 I/O0 (io), 10 I/O1 (io), 11 I/O2 (io), 12 NC, 13 I/O3 (io), 14 I/O4 (io), 15 I/O5 (io), 16 I/O6 (io), 17 I/O7 (io), 18 GND (power), 19 TDO/IN1 (io), 20 I/O8 (io), 21 I/O9 (io), 22 I/O10 (io), 23 I/O11 (io), 24 NC, 25 I/O12 (io), 26 I/O13 (io), 27 I/O14 (io), 28 I/O15 (io), 29 TCK/Y2 (in), 30 VCC (power), 31 ~{RESET} /Y1 (in), 32 TMS/NC (in), 33 I/O16 (io), 34 I/O17 (io), 35 I/O18 (io), 36 NC, 37 I/O19 (io), 38 I/O20 (io), 39 I/O21 (io), 40 I/O22 (io), 41 I/O23 (io), 42 GND (power), 43 GOE0 (in), 44 I/O24 (io), 45 I/O25 (io), 46 I/O26 (io), 47 I/O27 (io), 48 NC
